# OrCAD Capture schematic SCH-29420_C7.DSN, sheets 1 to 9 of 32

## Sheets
1 P01_FRONT_PAGE: title: i.MX 8QM CPU CARD; rev: C7; company: NXP Semiconductors; note: SOURCE: SCH-29420, PDF: SPF-29420; note: 6501 William Cannon Drive West; note: Austin, TX 78735-8598
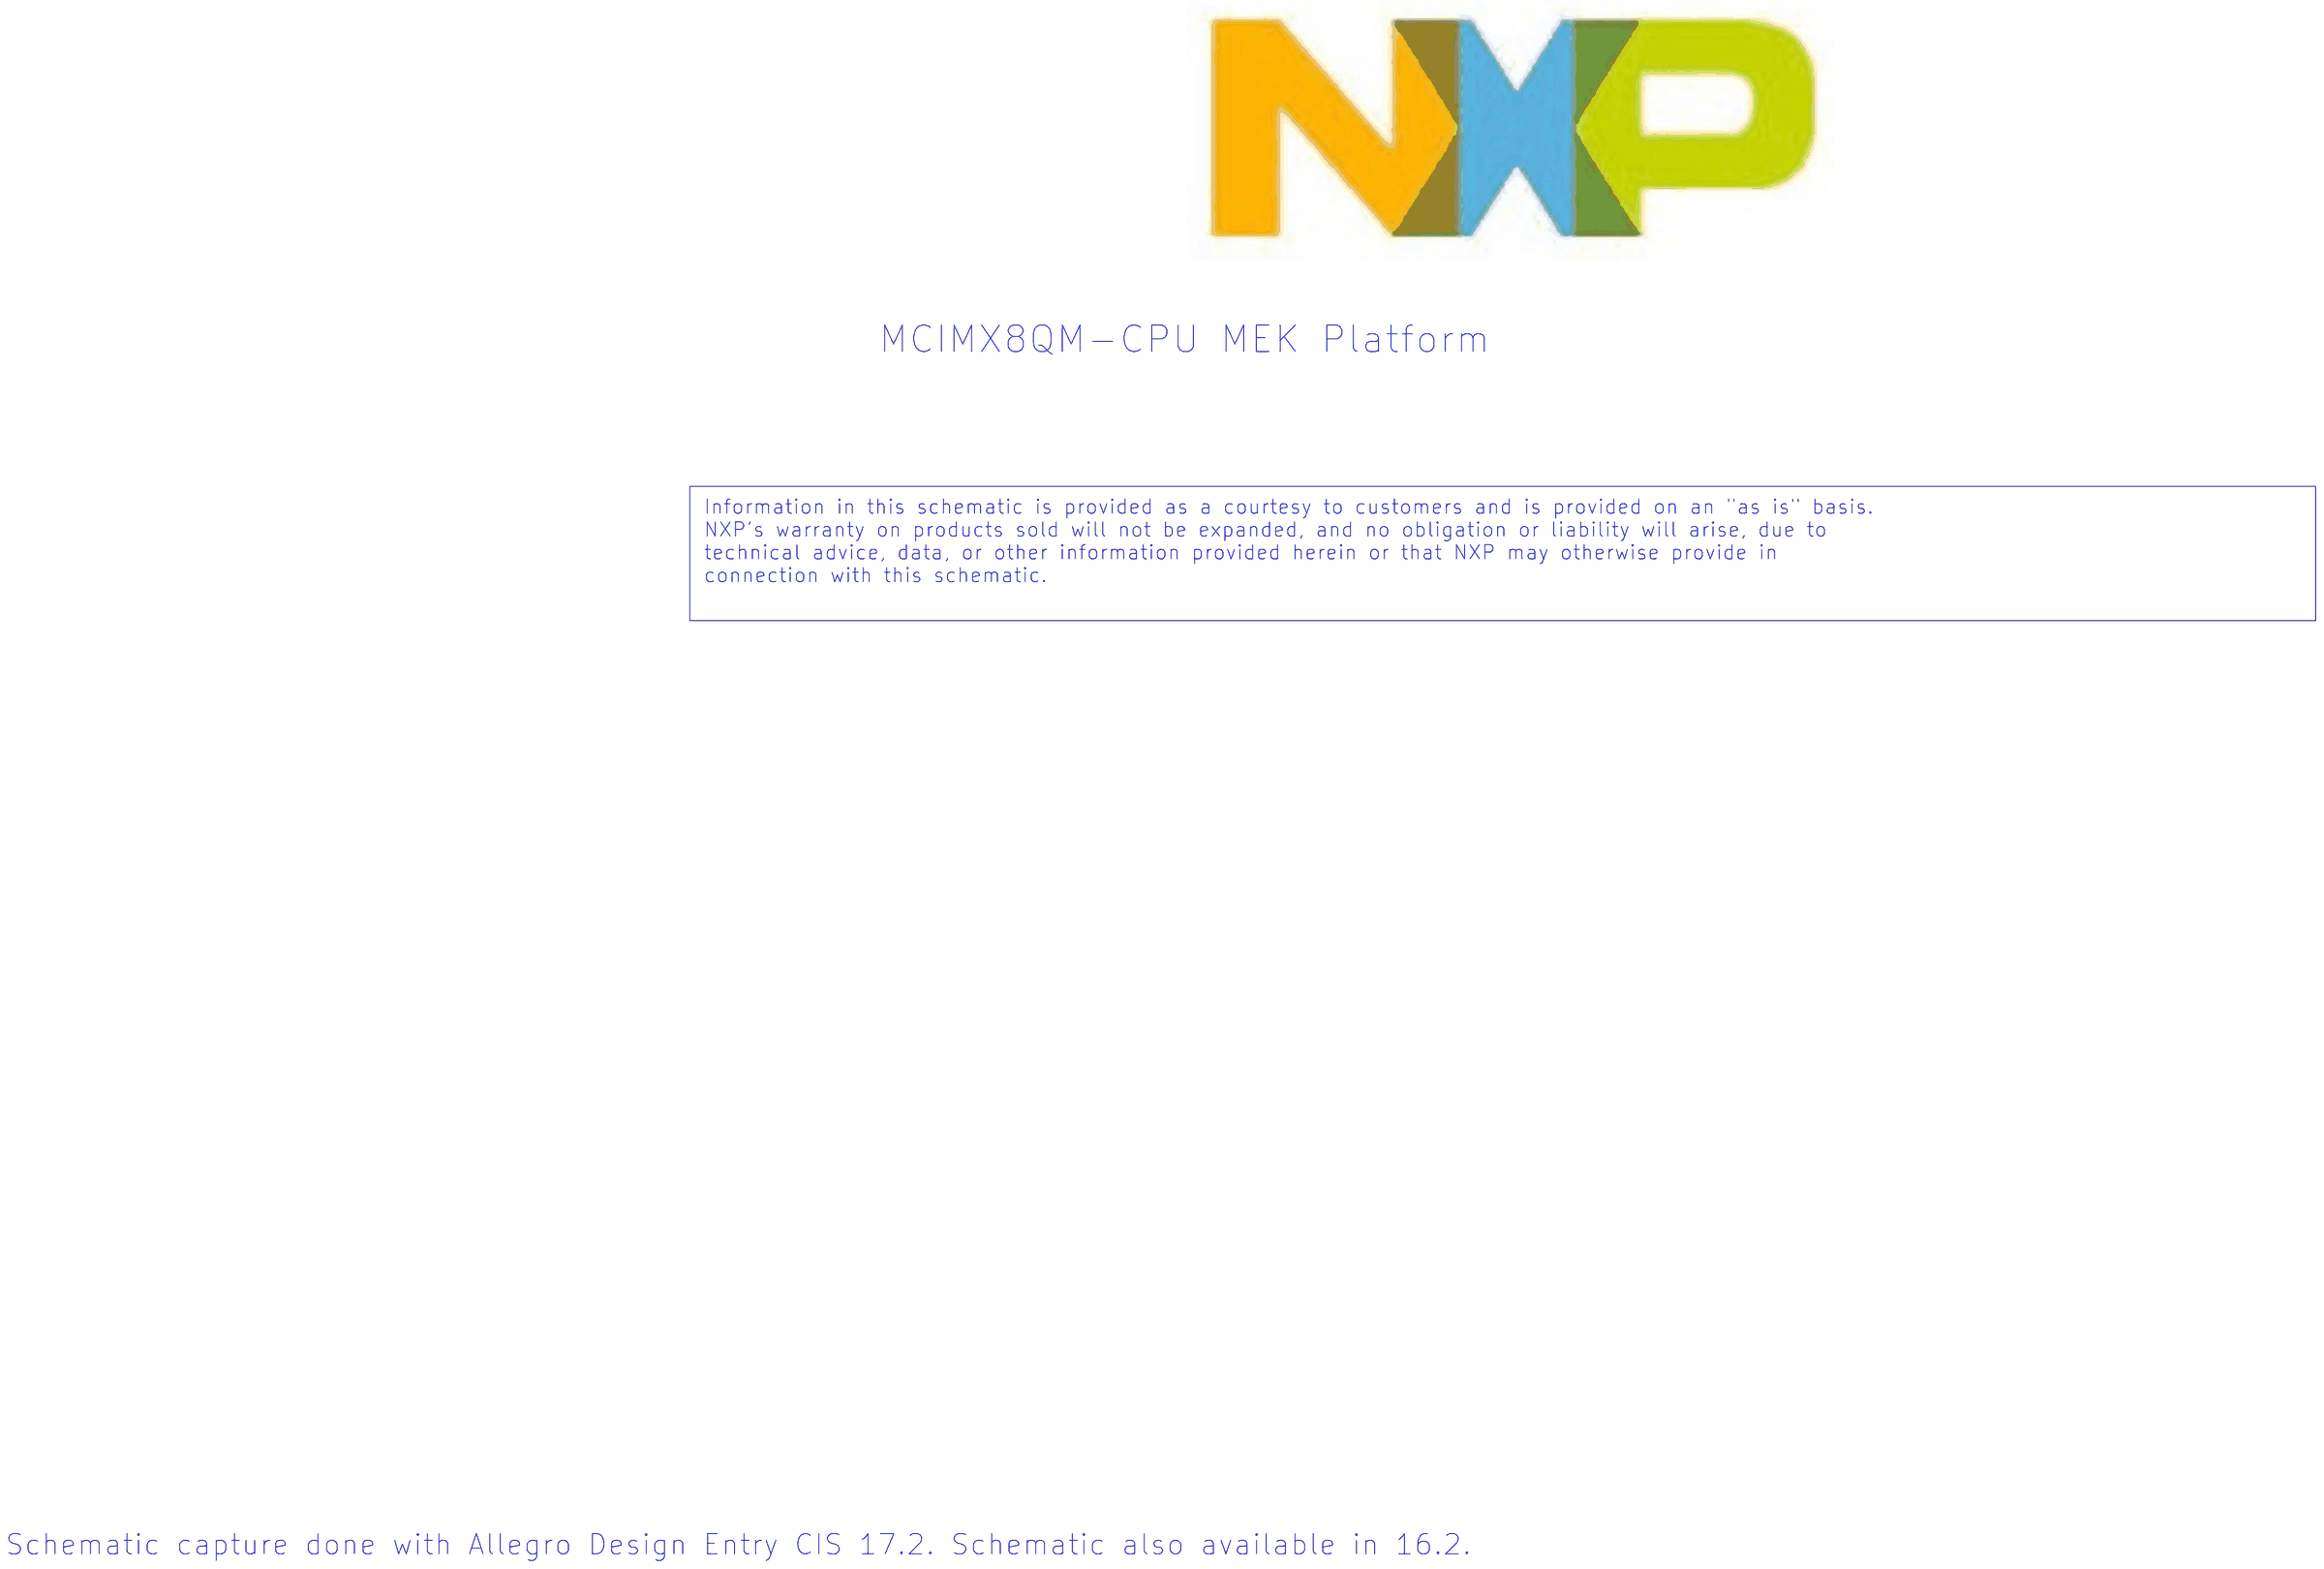
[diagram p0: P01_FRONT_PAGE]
2 P30_B2B_CONNETOR: size A2
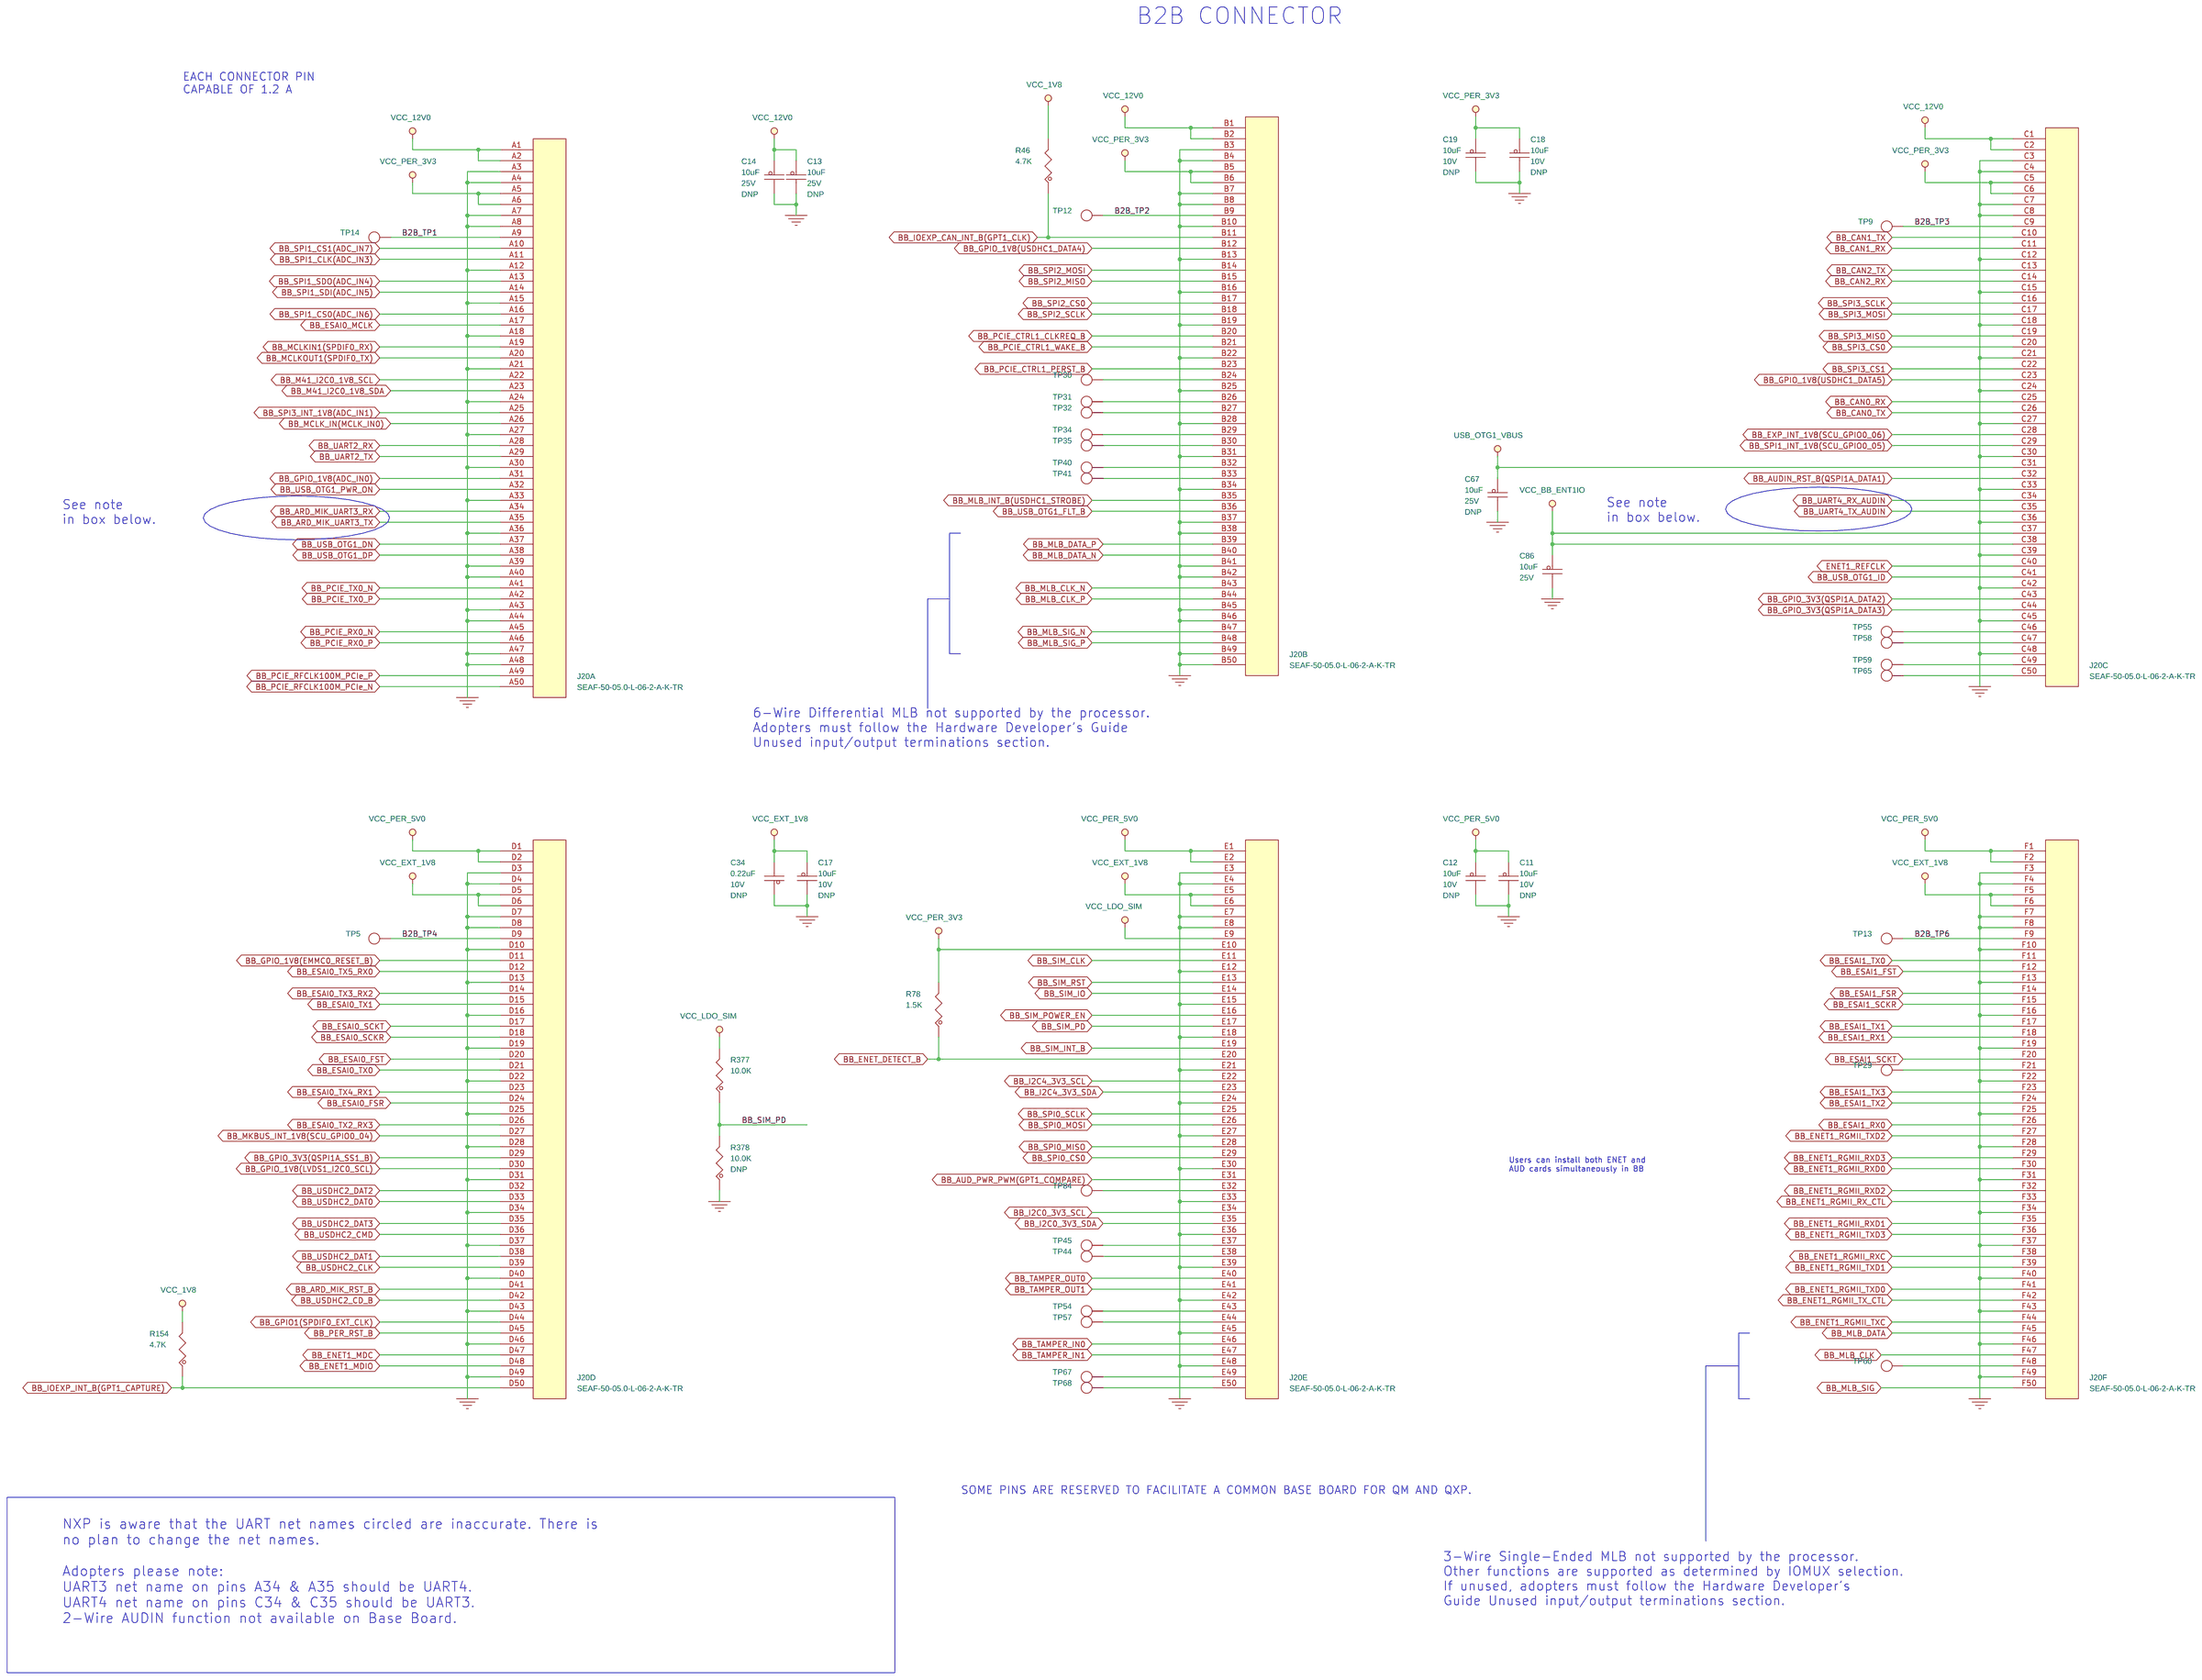
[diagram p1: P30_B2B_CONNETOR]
3 P06_I2C_TABLE
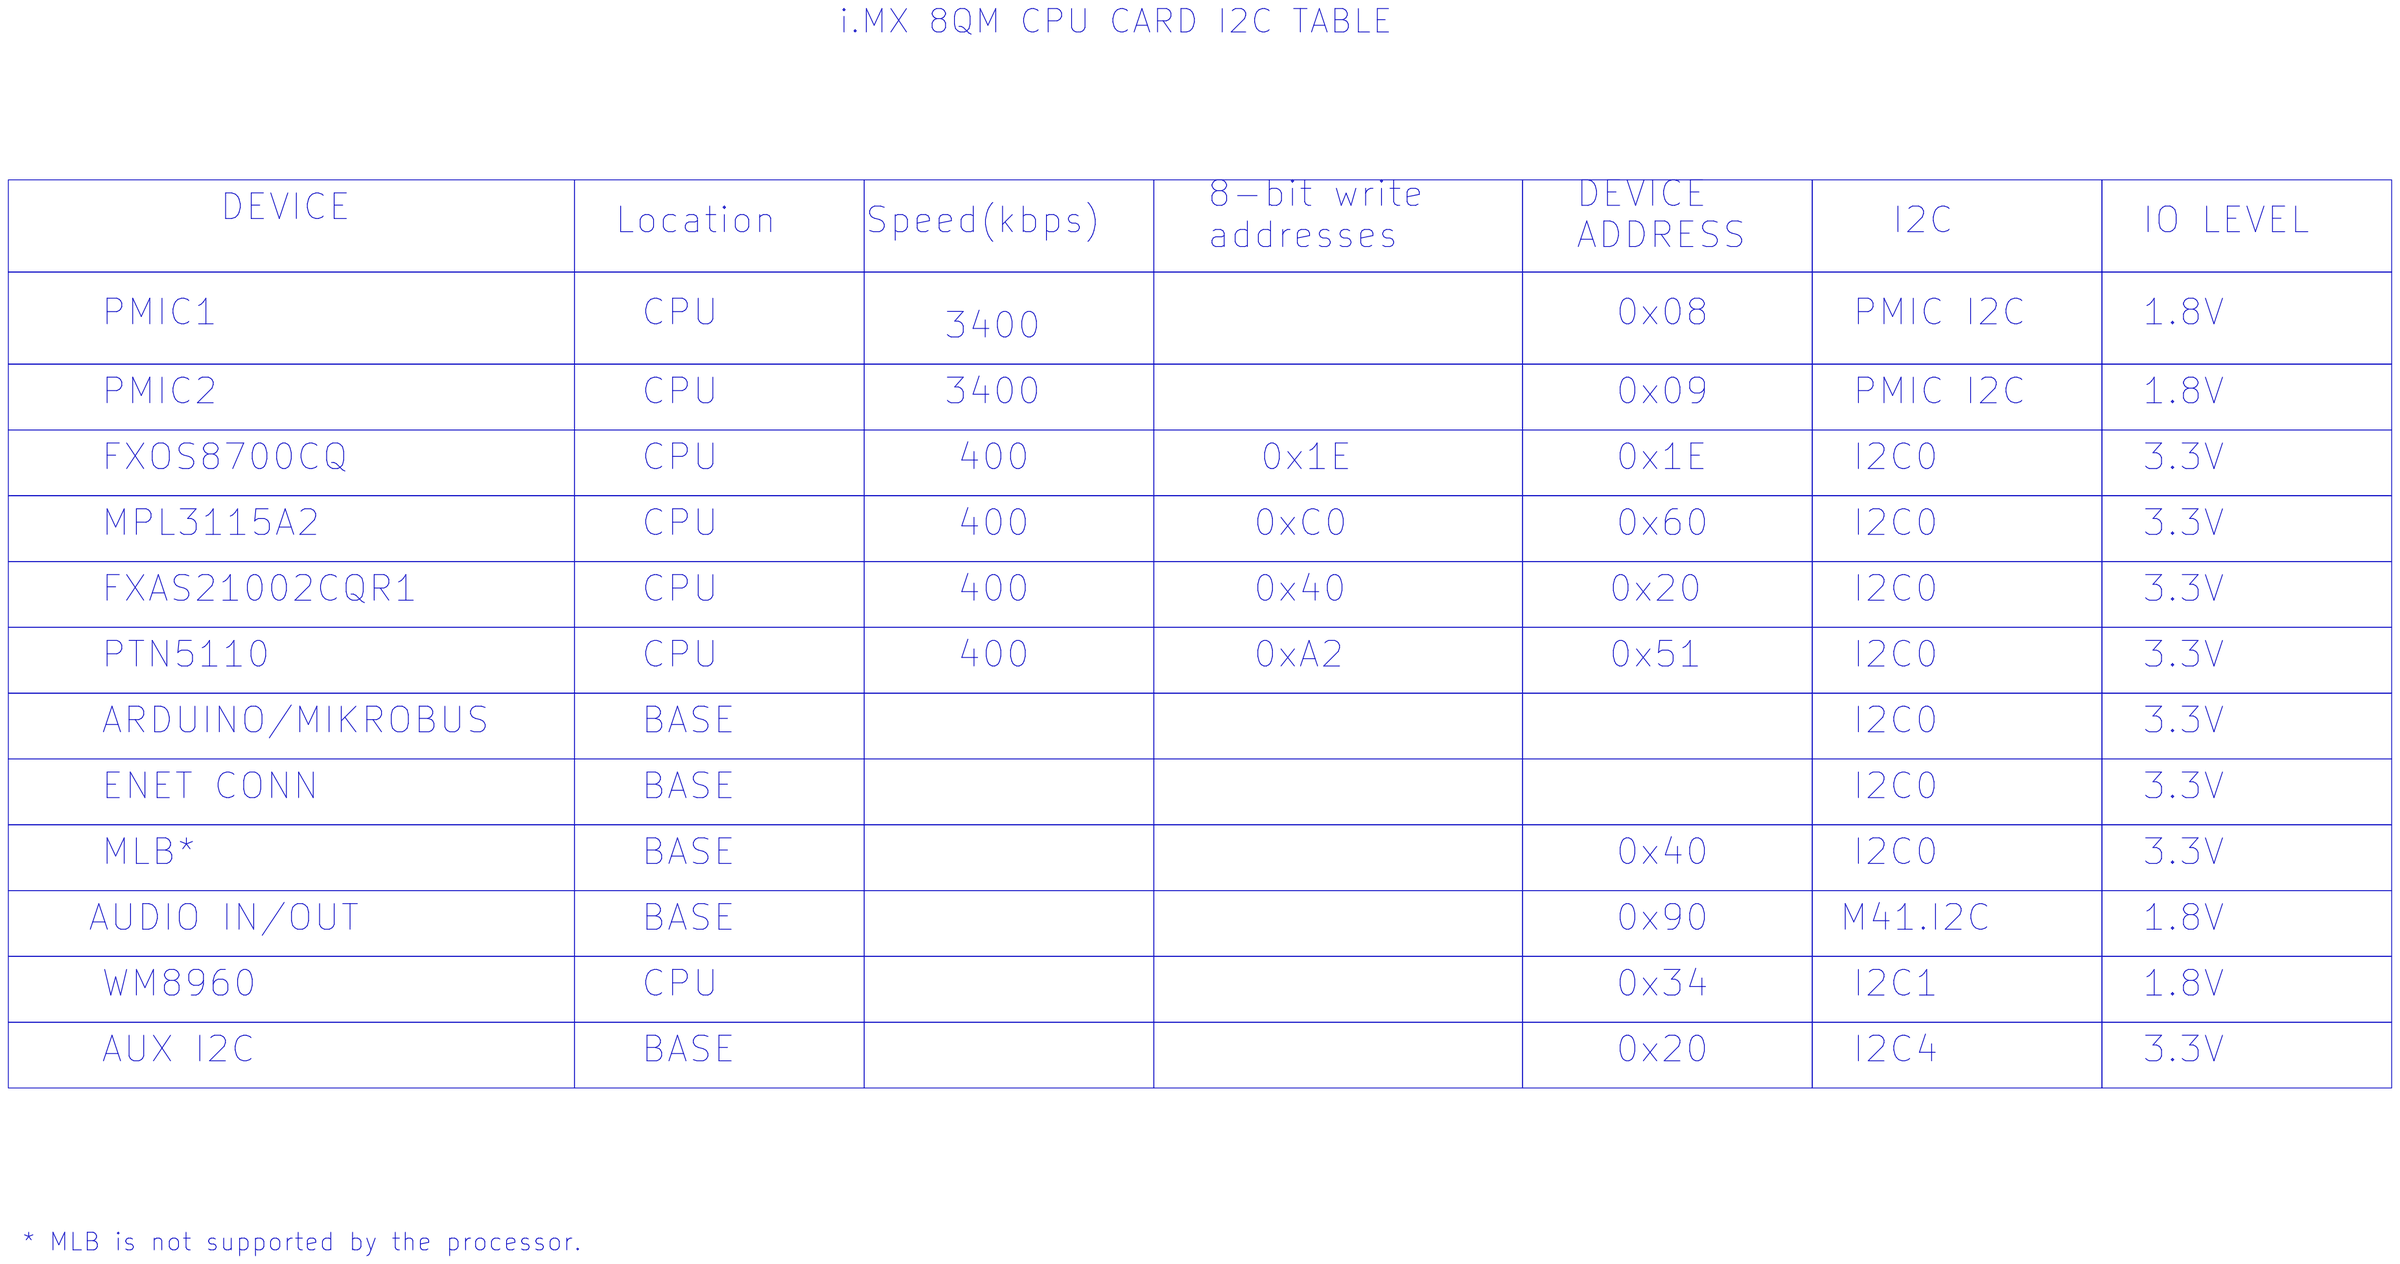
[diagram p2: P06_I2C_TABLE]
4 P05_BLOCK_DIAGRAM_RESET
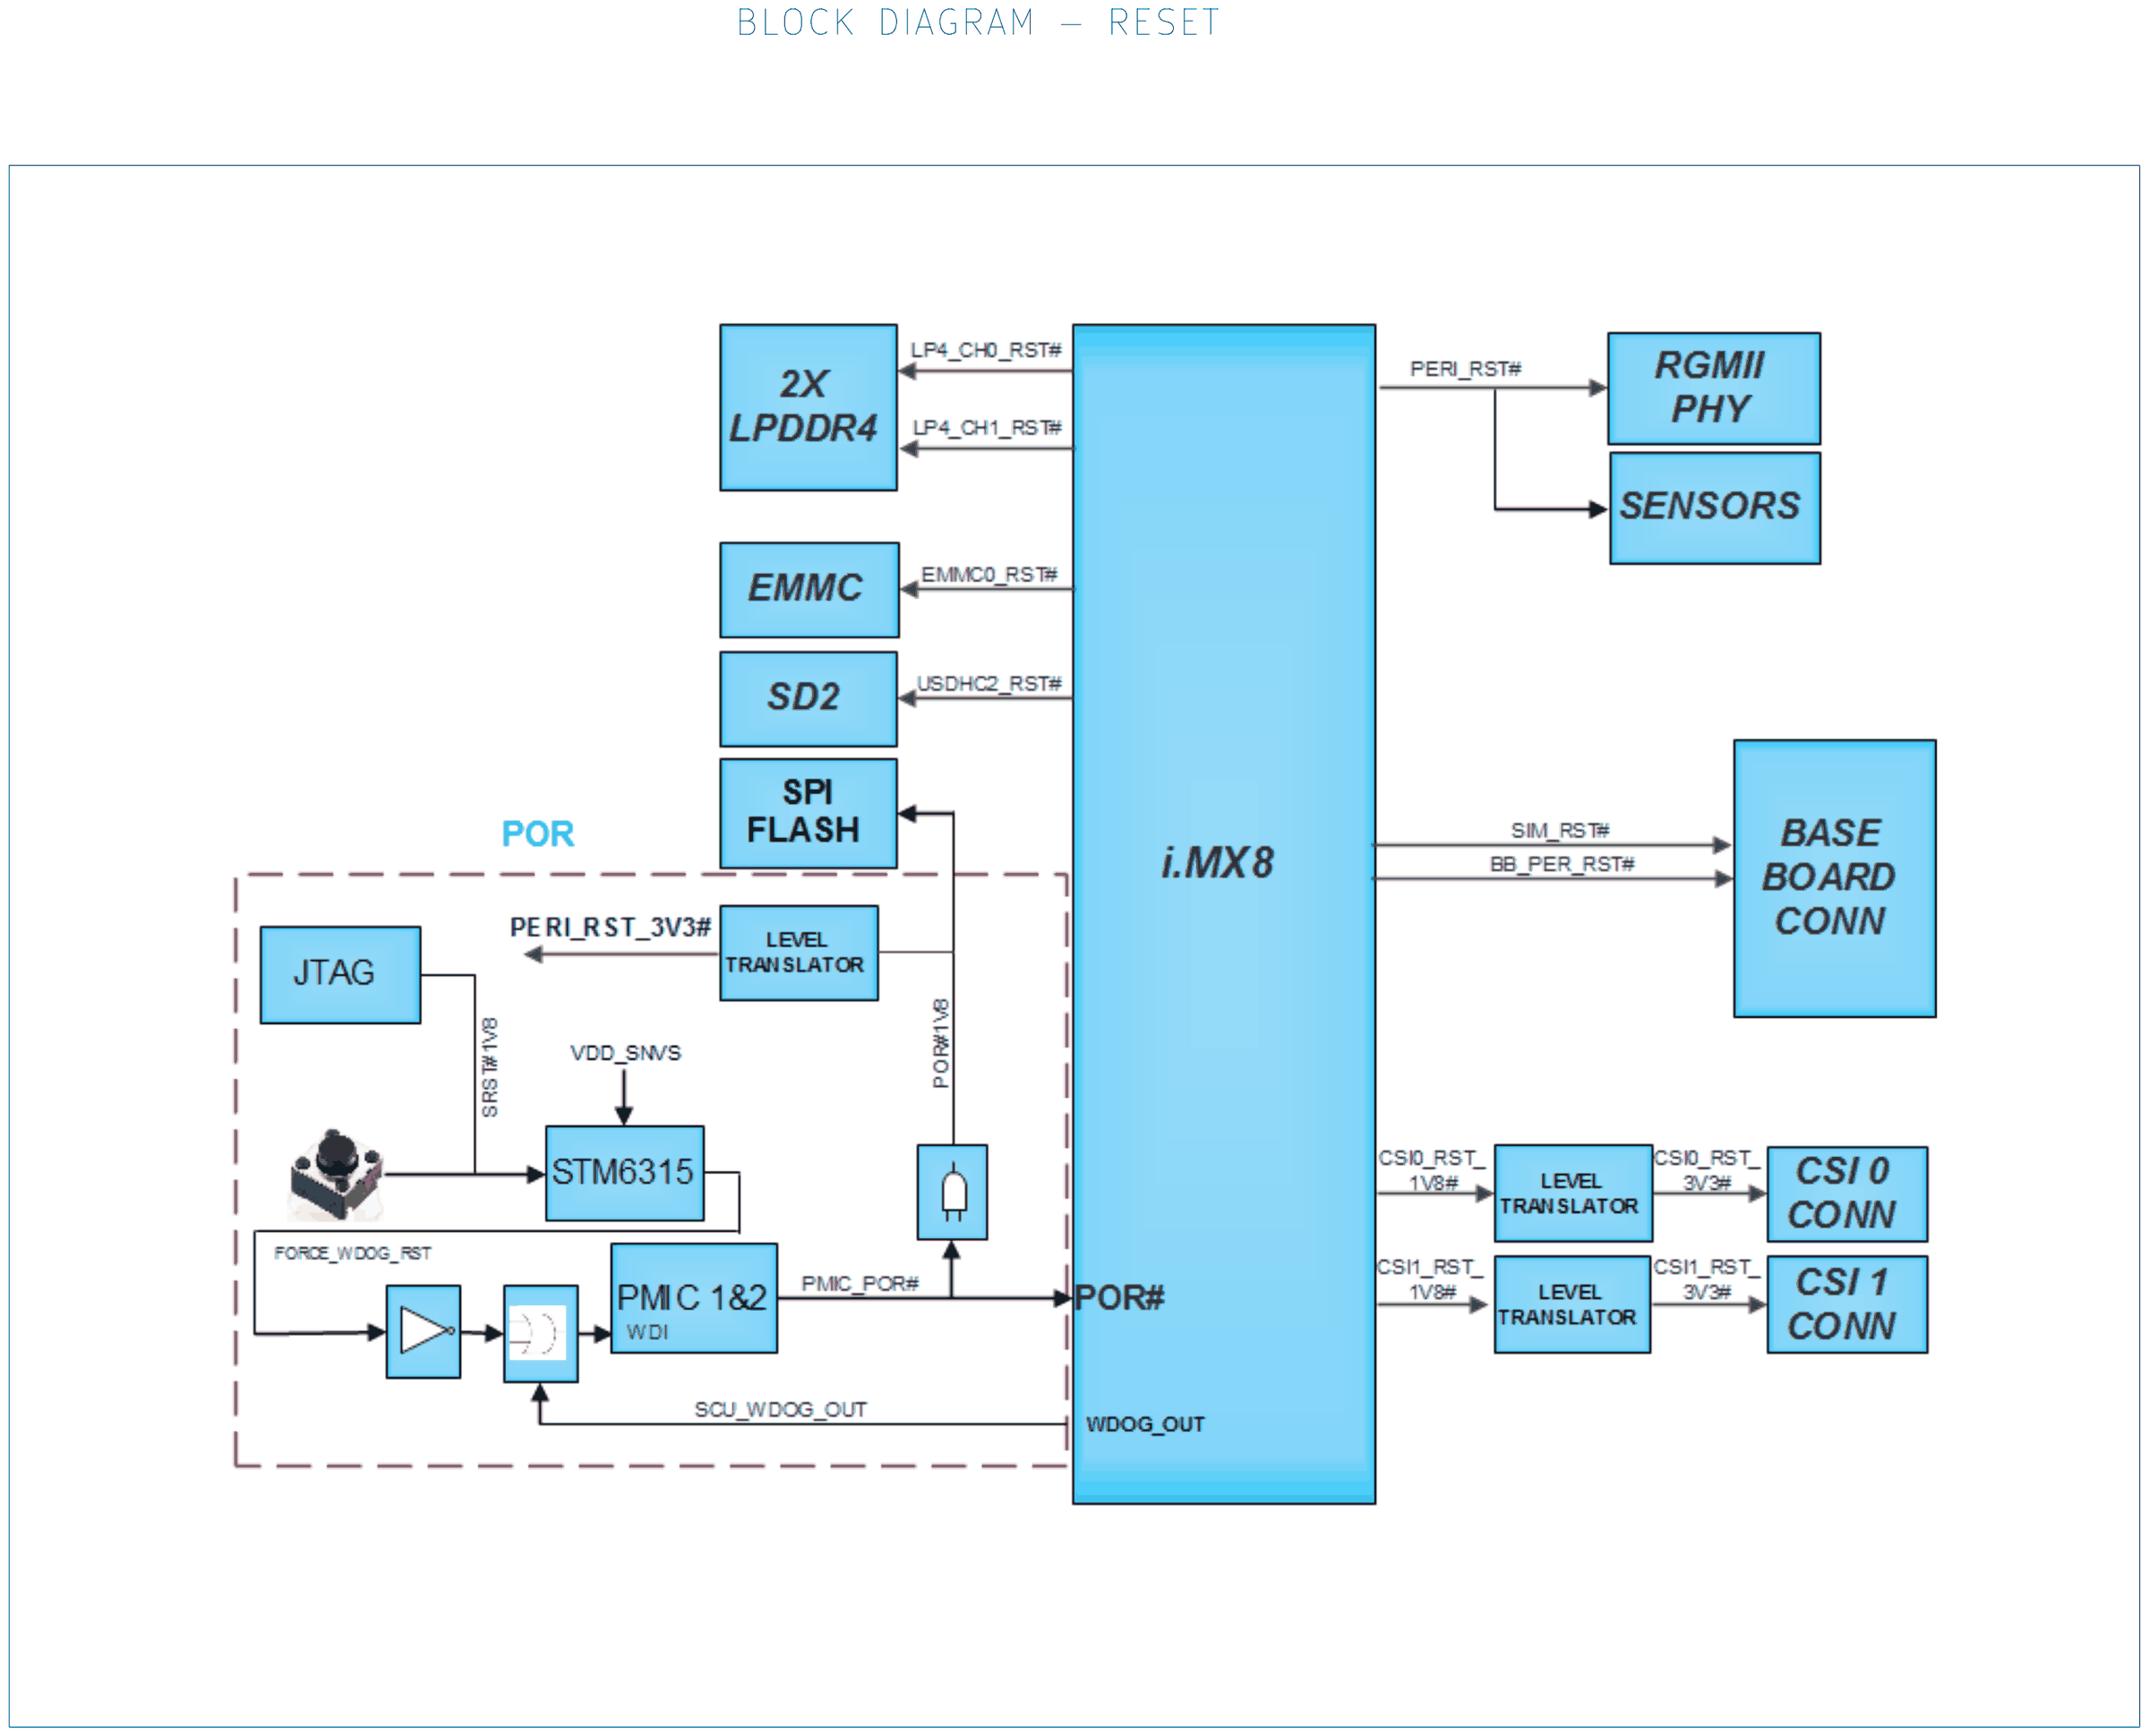
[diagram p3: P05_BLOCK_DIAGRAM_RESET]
5 P29_MIPI_DSI_CONNECTORS: size A2
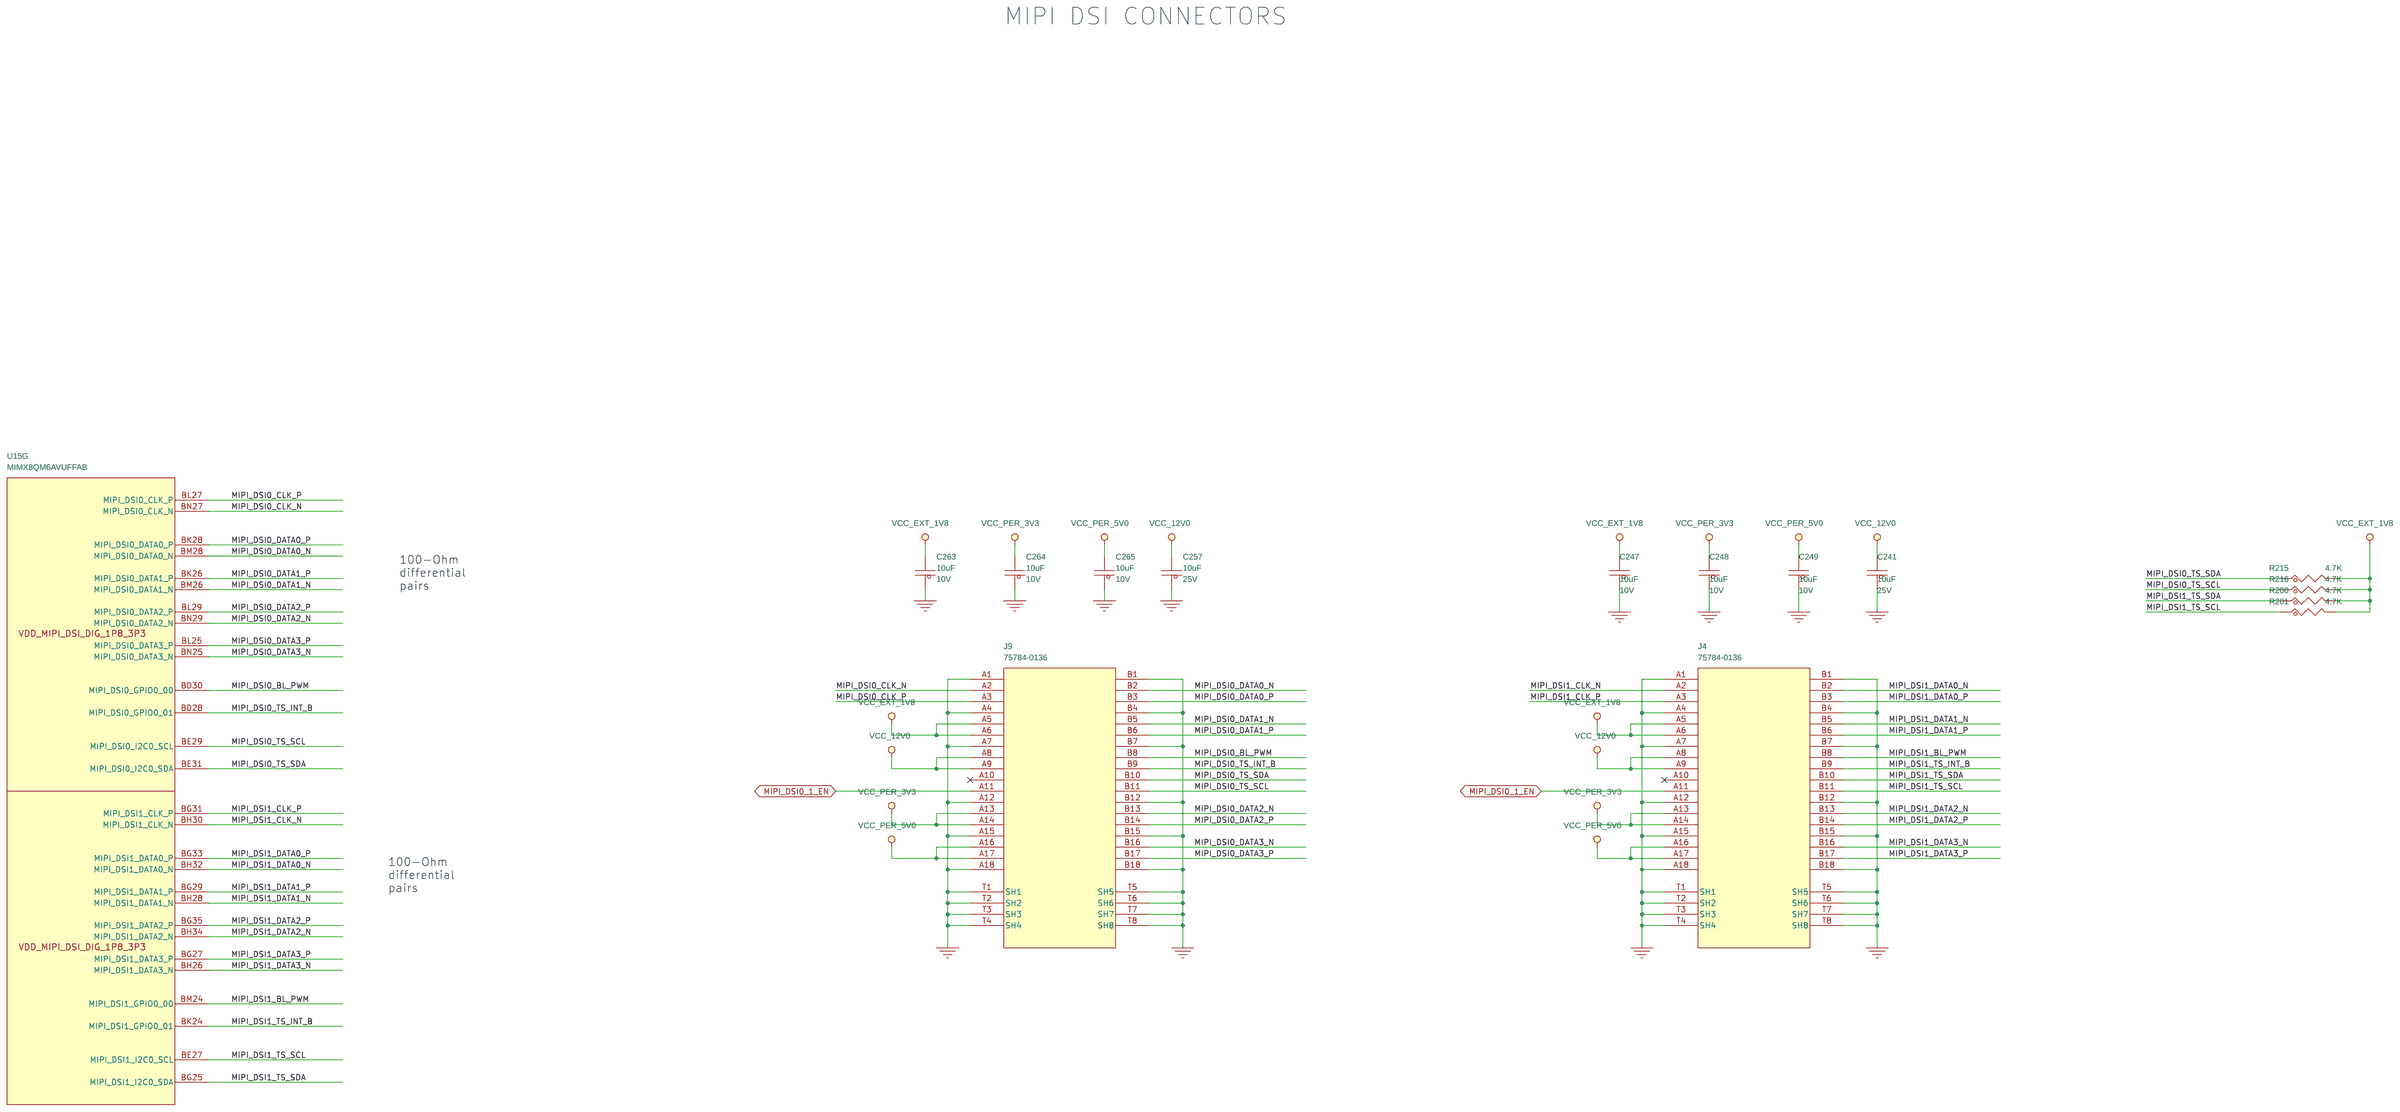
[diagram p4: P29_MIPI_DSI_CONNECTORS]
6 P09_PMIC_2: size A2
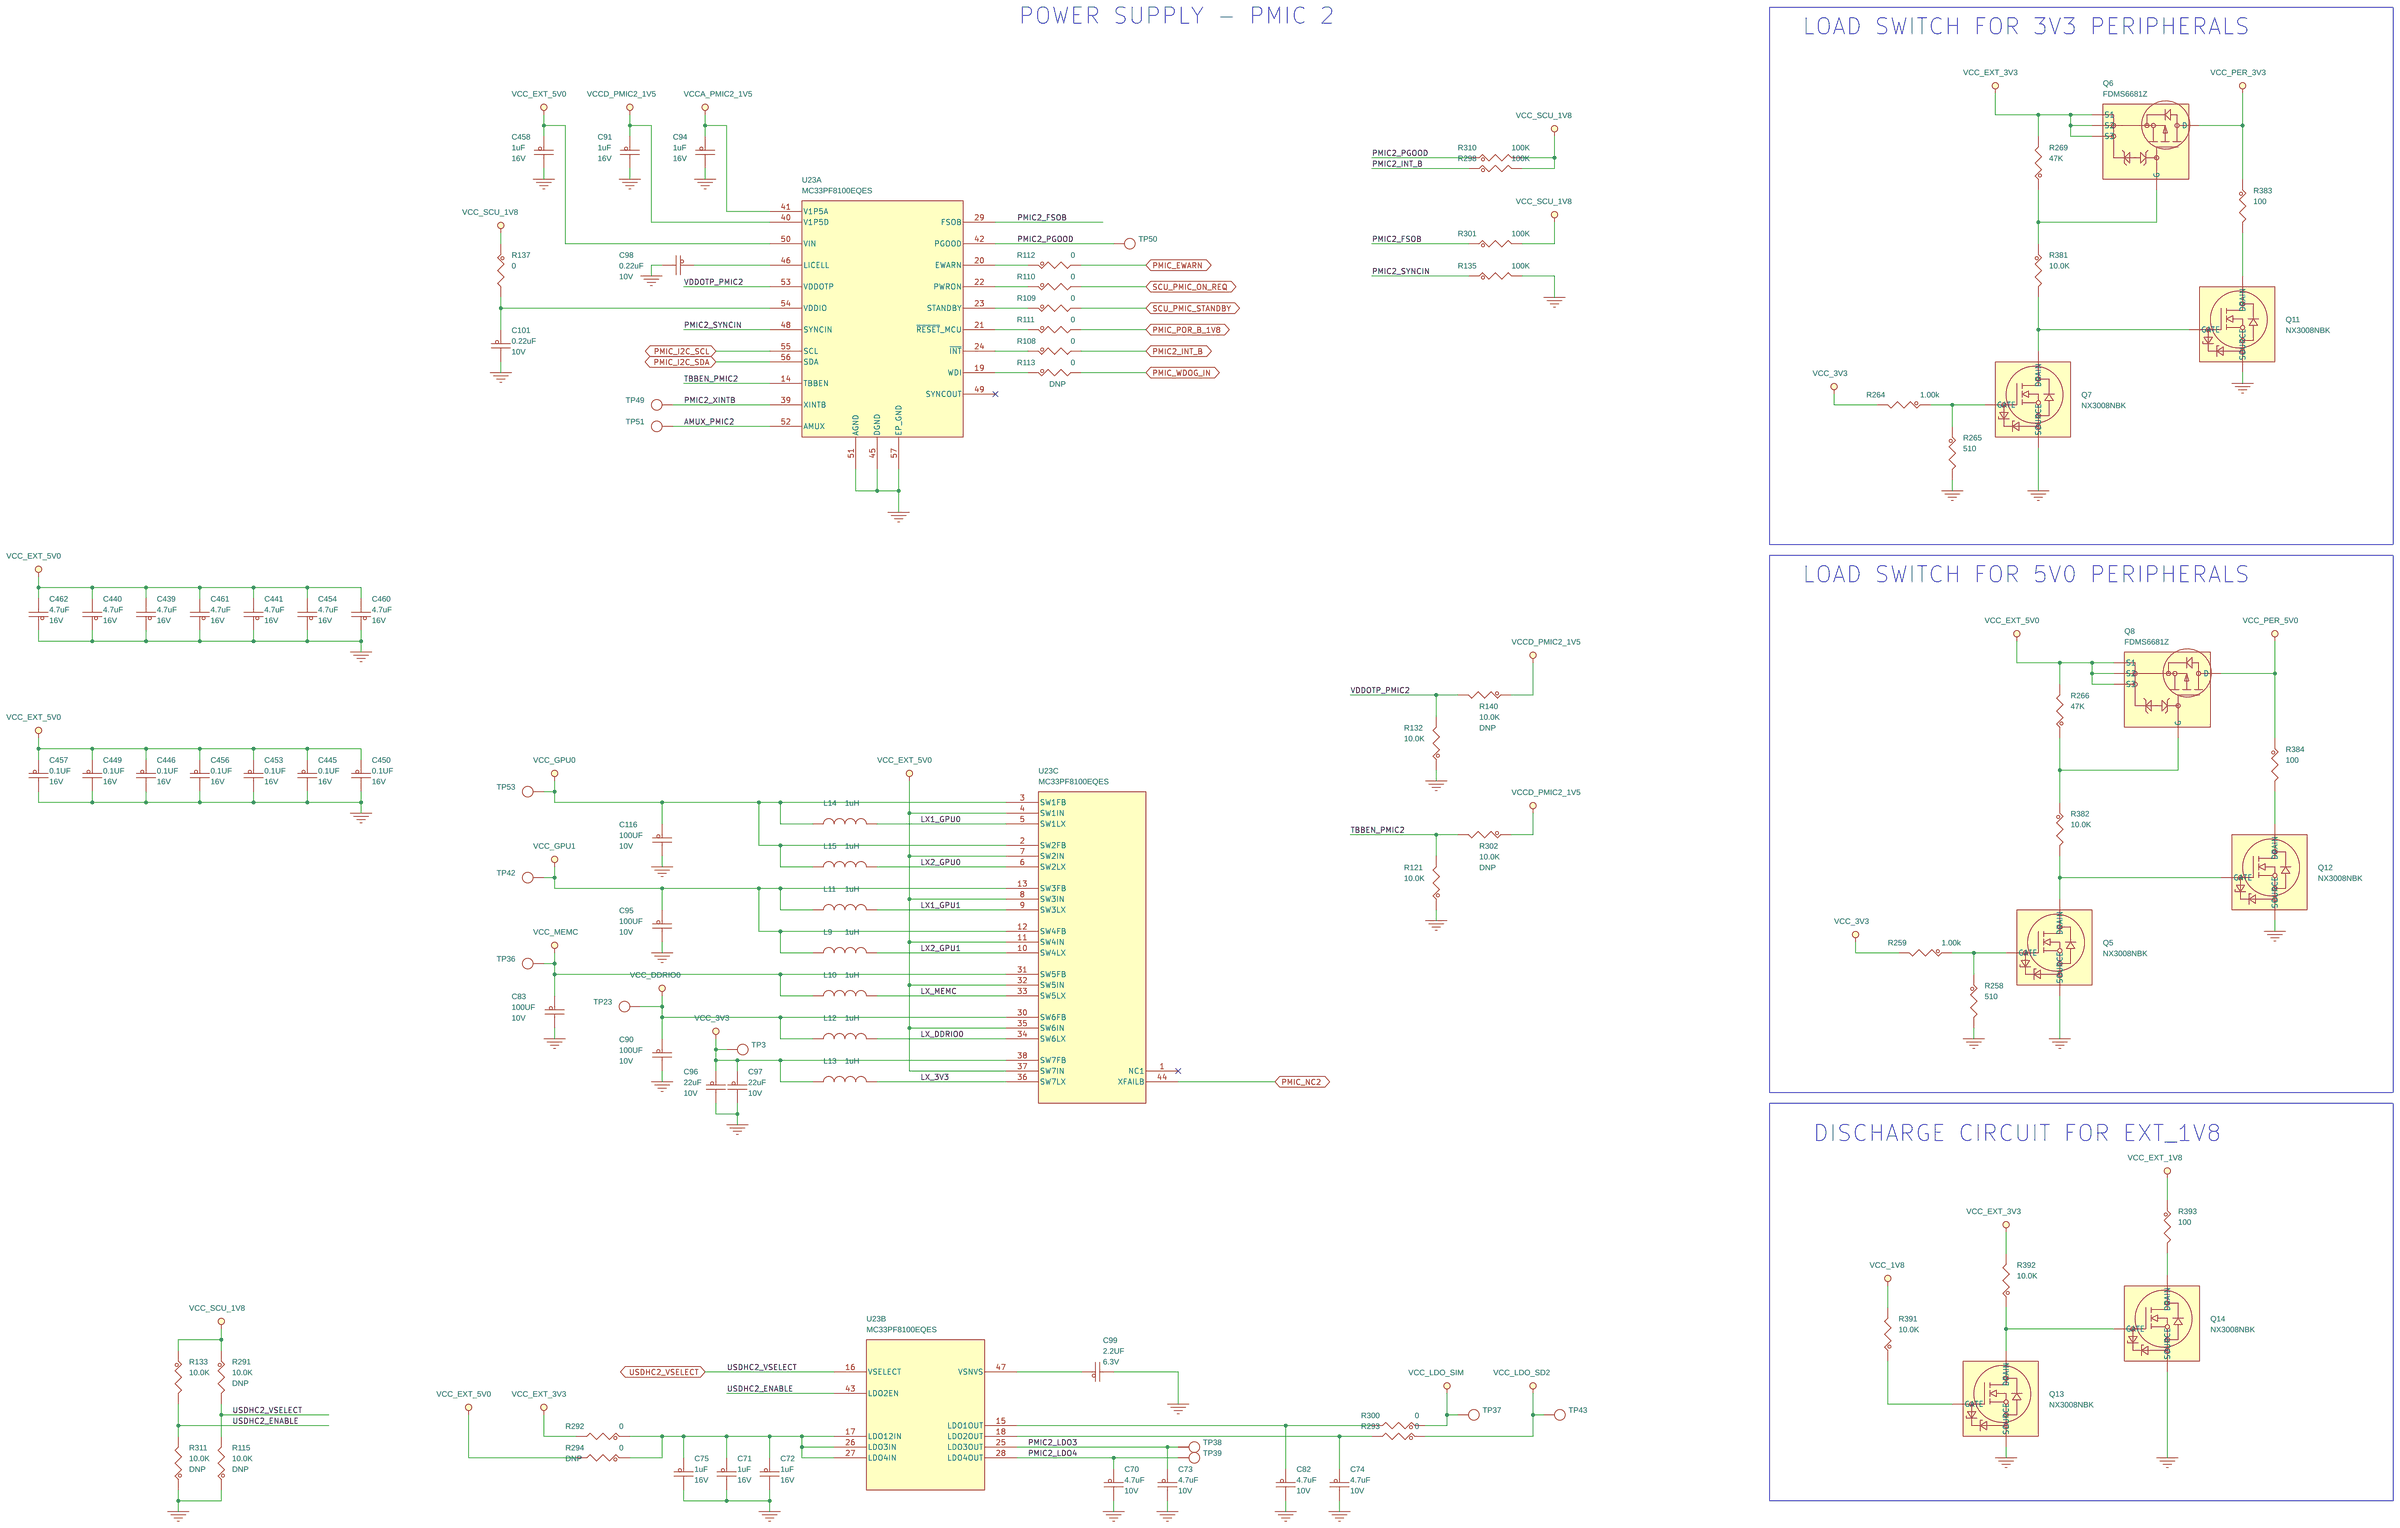
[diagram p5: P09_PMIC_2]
7 P04_BLOCK_DIAGRAM_POWER
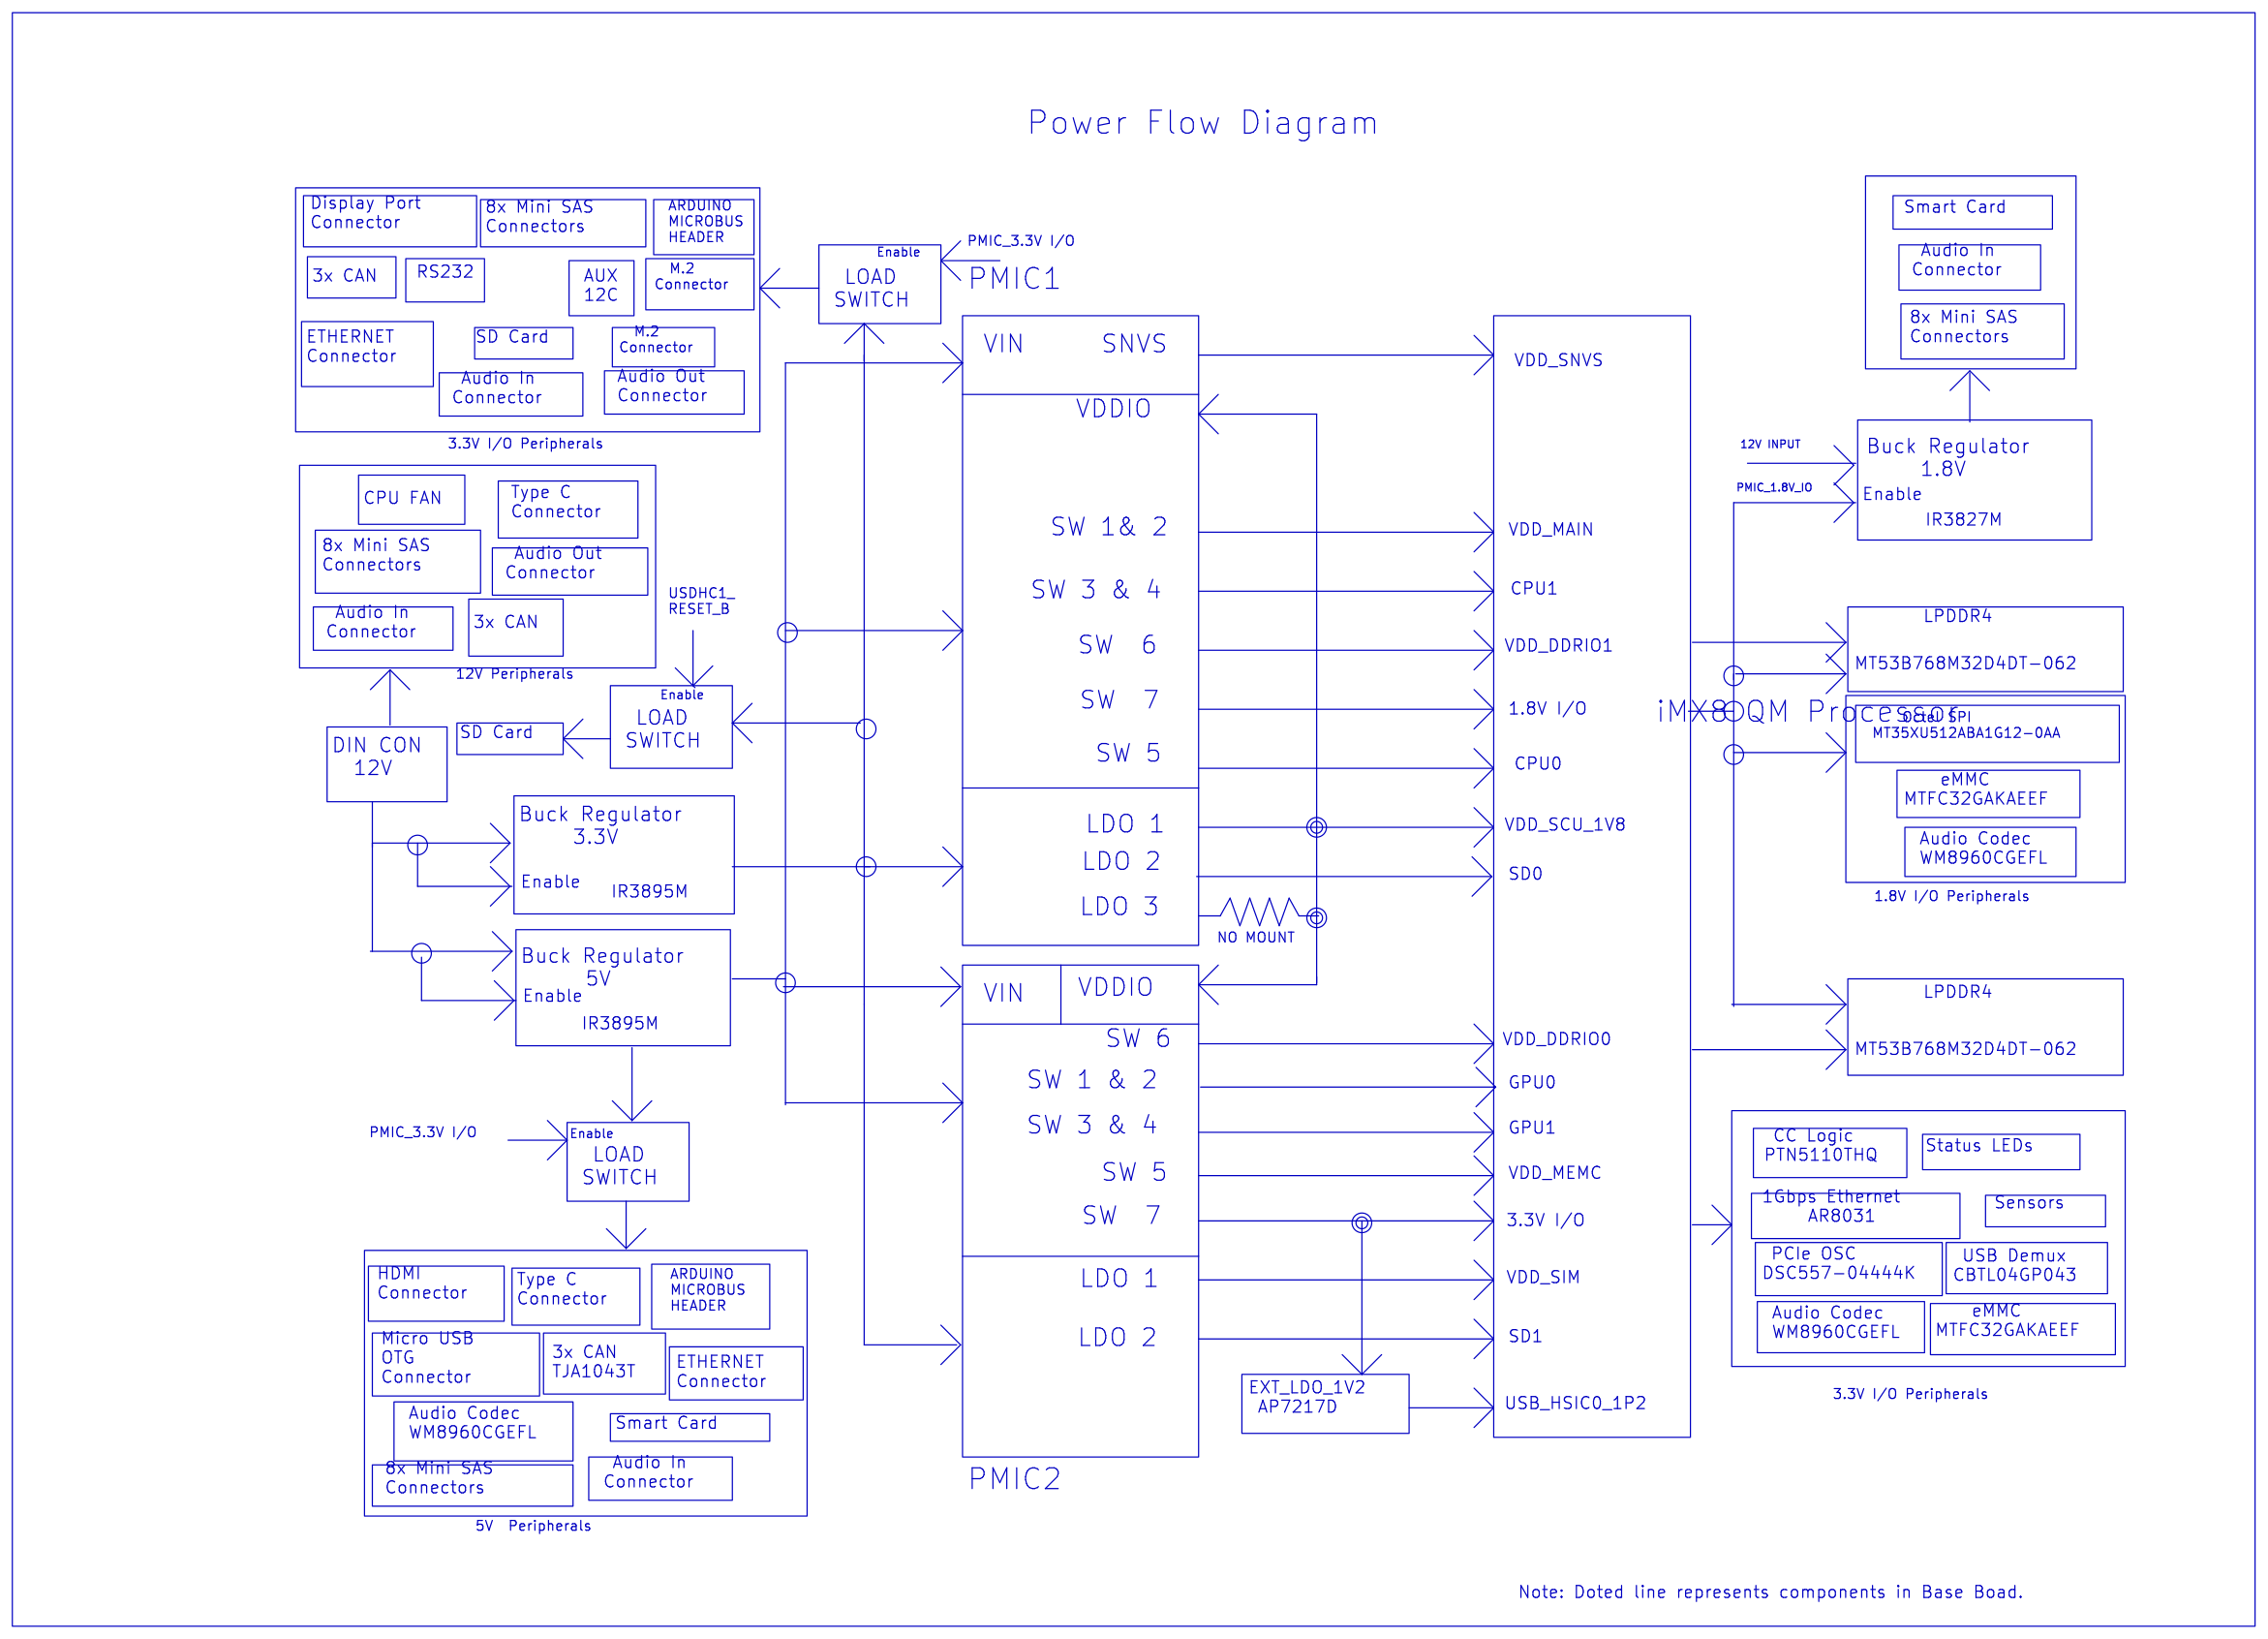
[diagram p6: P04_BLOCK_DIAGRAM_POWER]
8 P02_TITLE_PAGE
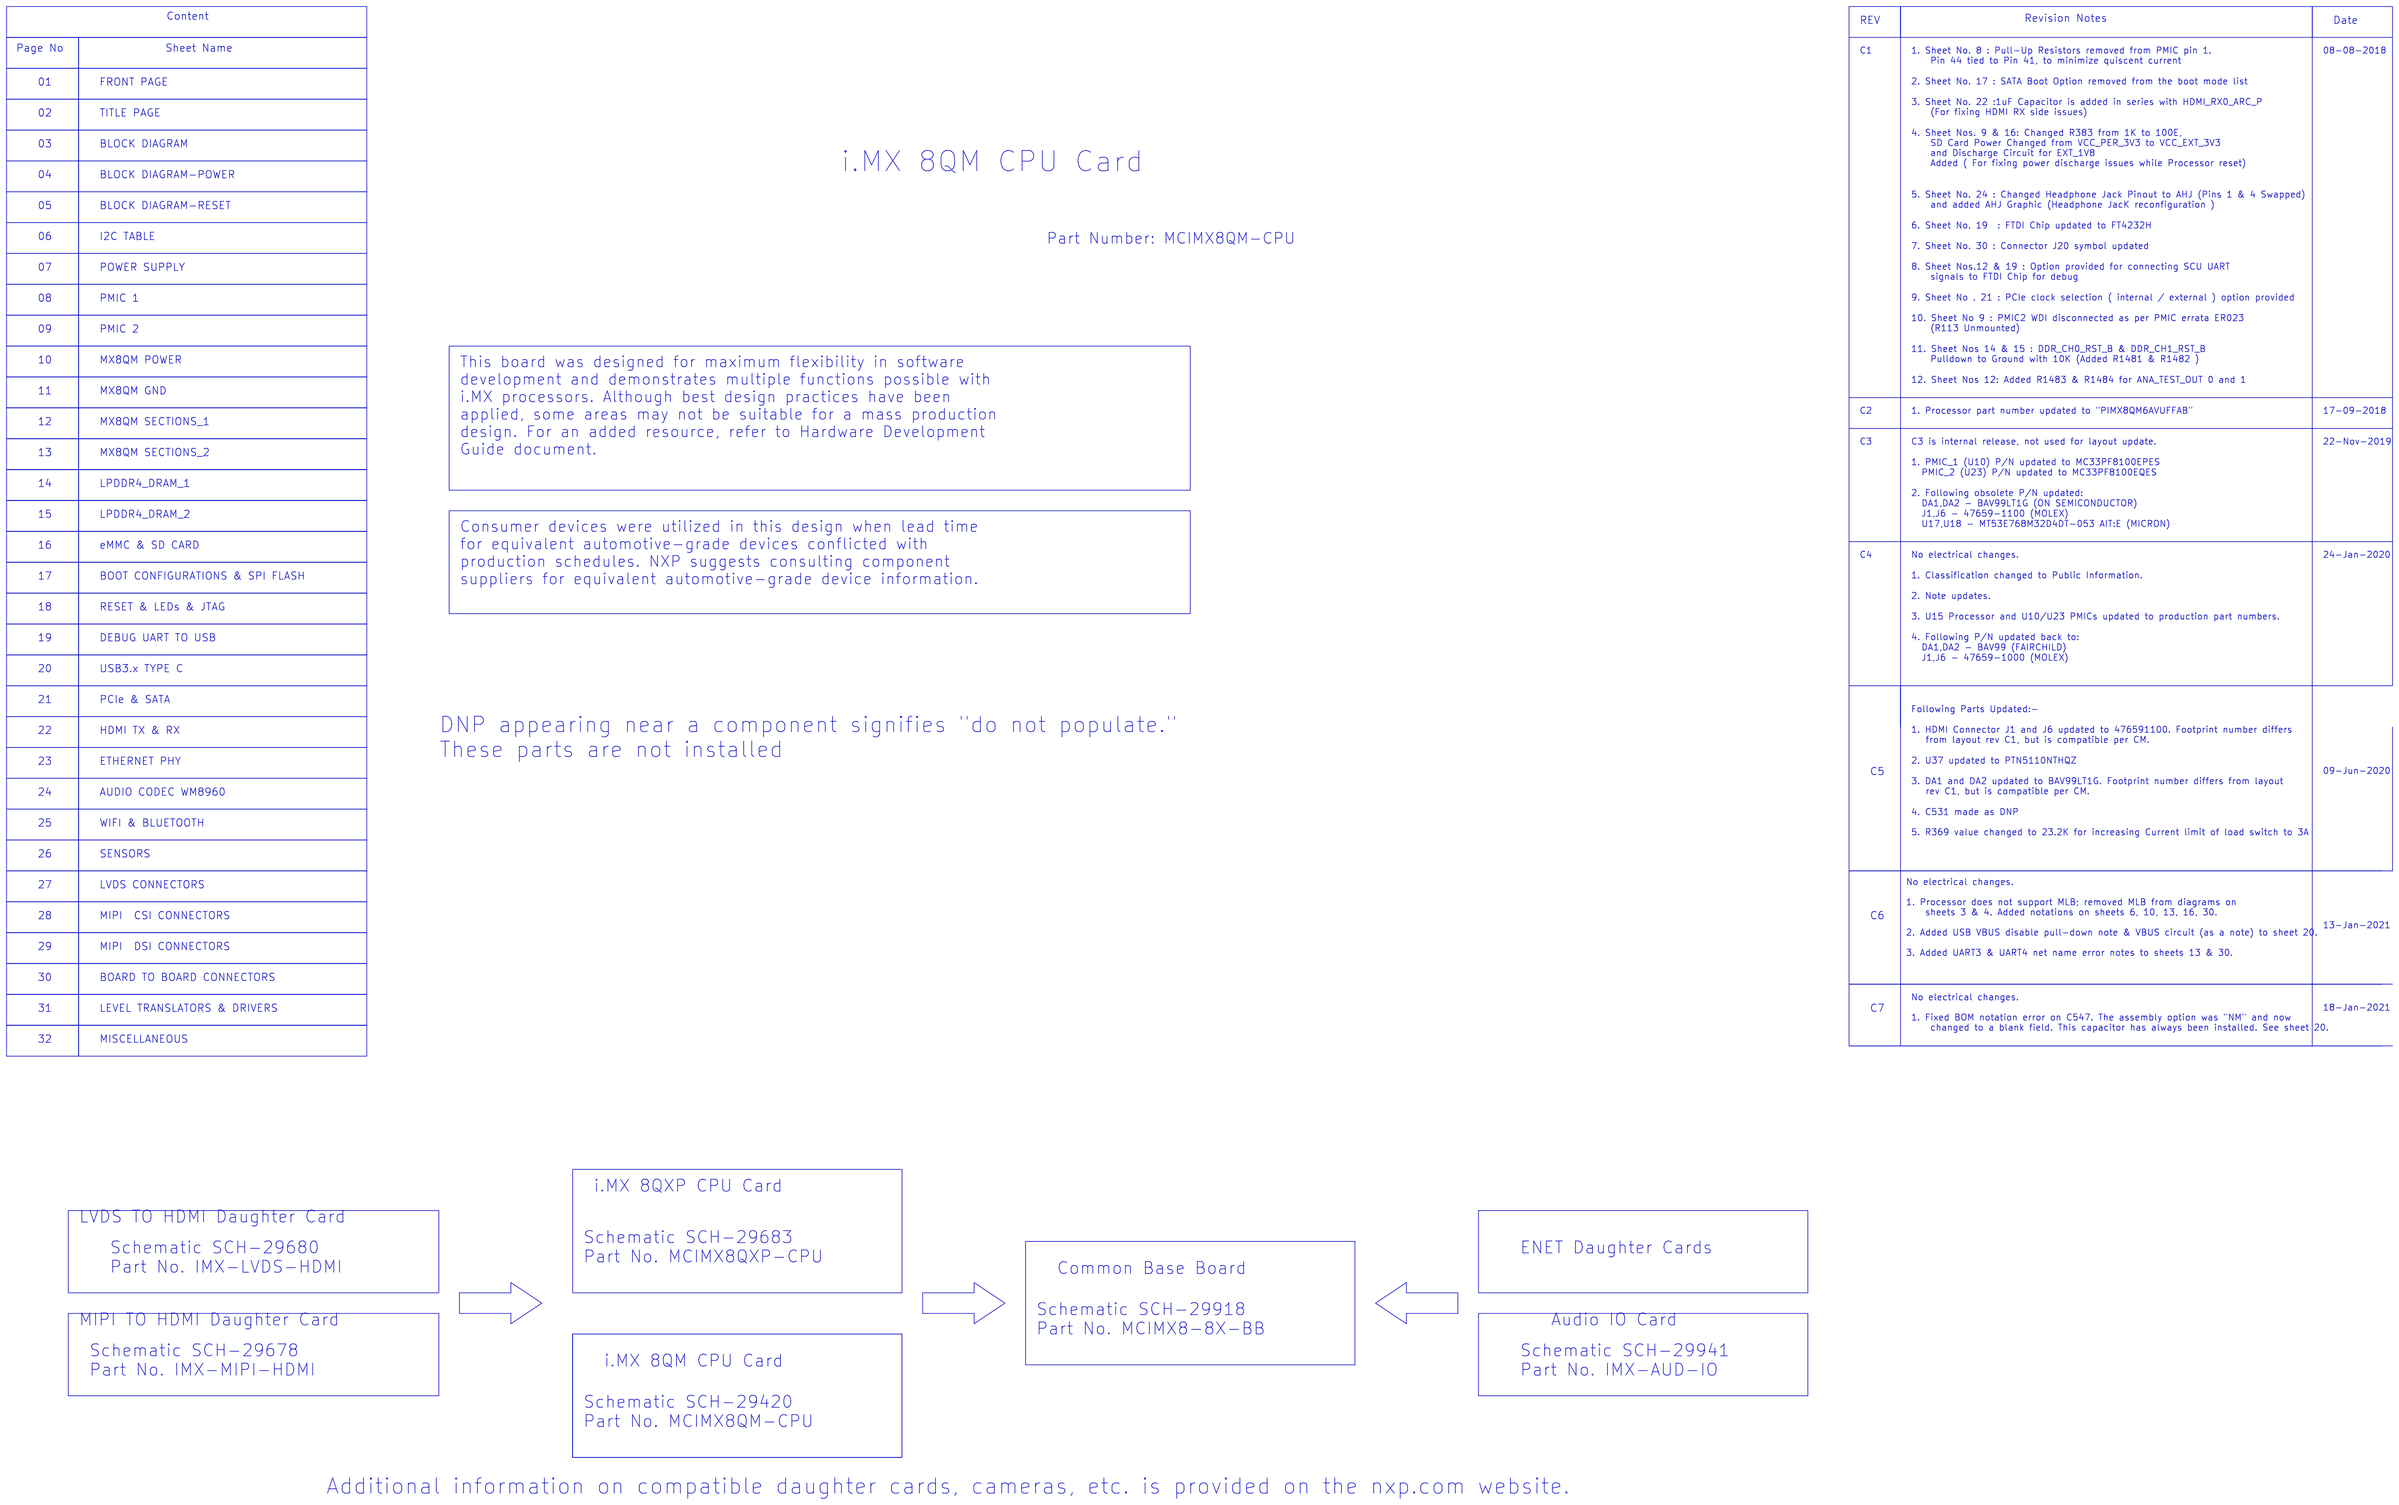
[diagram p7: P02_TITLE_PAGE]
9 P03_BLOCK_DIAGRAM
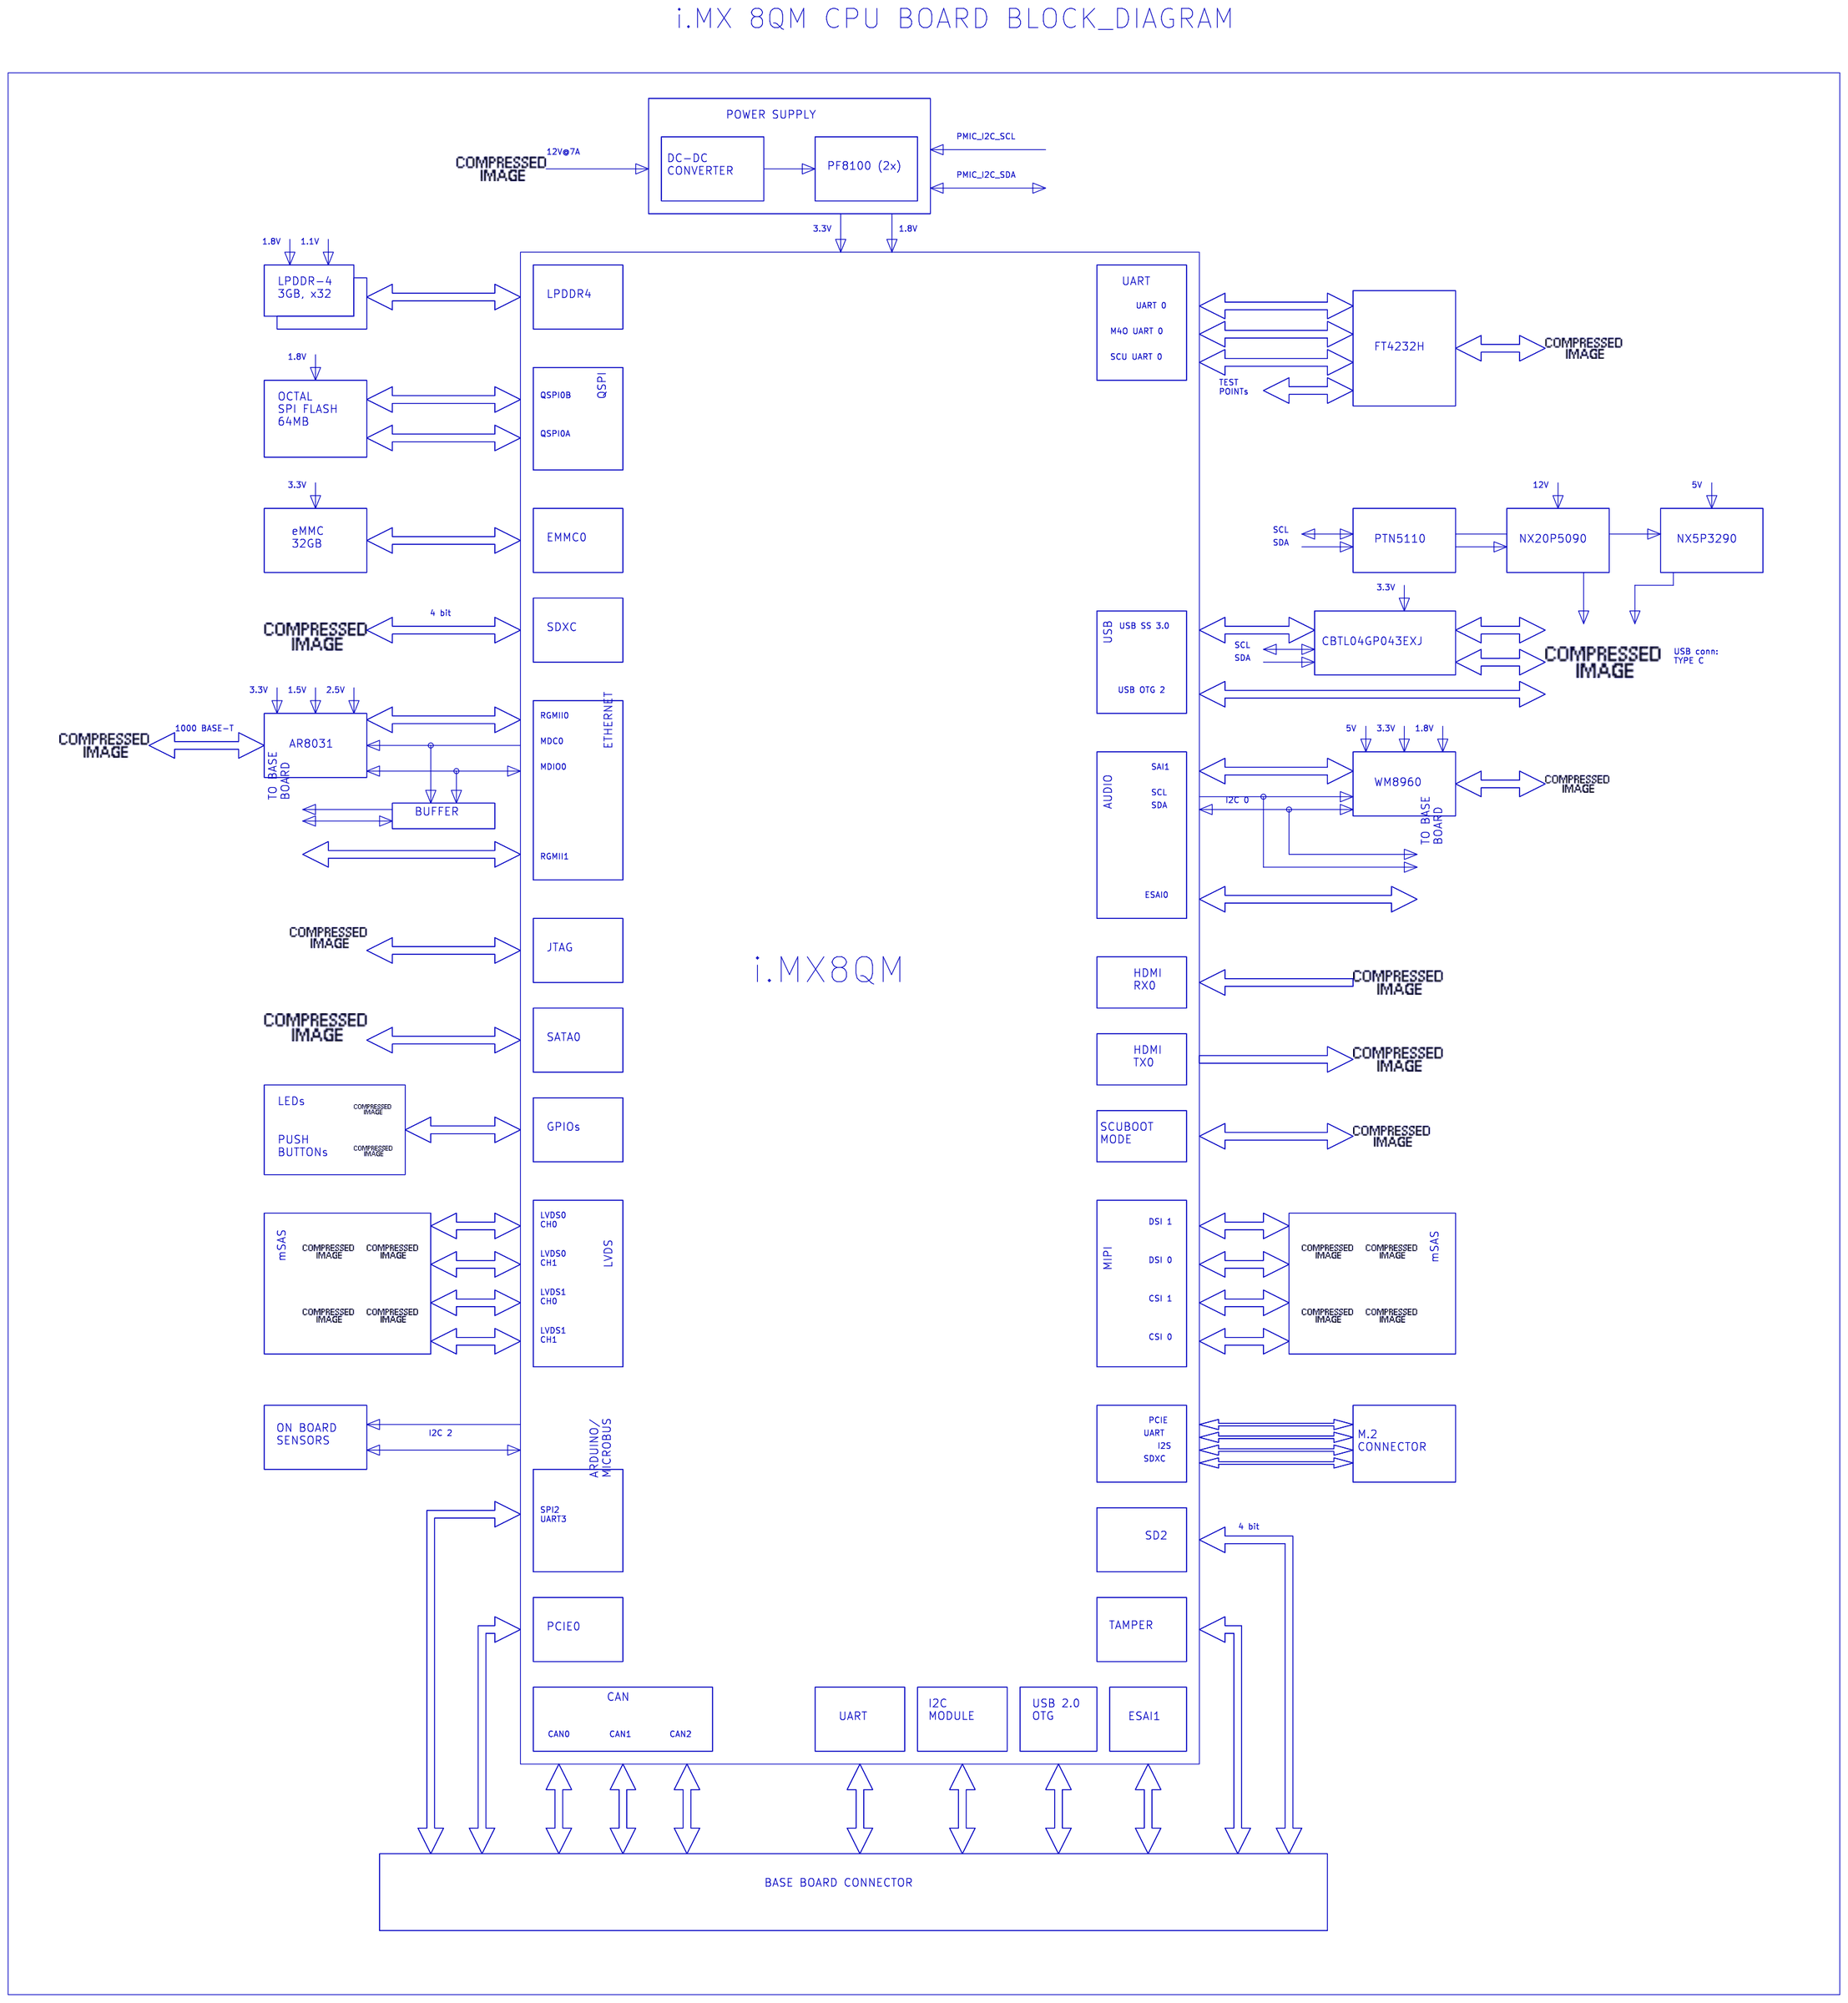
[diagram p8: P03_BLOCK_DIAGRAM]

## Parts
sheet P09_PMIC_2
C70  4.7uF  [CC0402_25]
C71  1uF  [CC0402_25]
C72  1uF  [CC0402_25]
C73  4.7uF  [CC0402_25]
C74  4.7uF  [CC0402_25]
C75  1uF  [CC0402_25]
C82  4.7uF  [CC0402_25]
C83  100UF  [CC1210]
C90  100UF  [CC1210]
C91  1uF  [CC0402_25]
C94  1uF  [CC0402_25]
C95  100UF  [CC1210]
C96  22uF  [CC0603_OV]
C97  22uF  [CC0603_OV]
C98  0.22uF  [CC0402_25]
C99  2.2UF  [CC0402_25]
C101  0.22uF  [CC0402_25]
C116  100UF  [CC1210]
C439  4.7uF  [CC0603_OV]
C440  4.7uF  [CC0603_OV]
C441  4.7uF  [CC0603_OV]
C445  0.1UF  [CC0402_25]
C446  0.1UF  [CC0402_25]
C449  0.1UF  [CC0402_25]
C450  0.1UF  [CC0402_25]
C453  0.1UF  [CC0402_25]
C454  4.7uF  [CC0603_OV]
C456  0.1UF  [CC0402_25]
C457  0.1UF  [CC0402_25]
C458  1uF  [CC0402_25]
C460  4.7uF  [CC0603_OV]
C461  4.7uF  [CC0603_OV]
C462  4.7uF  [CC0603_OV]
L9  1uH  [ind2520]
L10  1uH  [ind2520]
L11  1uH  [ind2520]
L12  1uH  [ind2520]
L13  1uH  [ind2520]
L14  1uH  [ind2520]
L15  1uH  [ind2520]
Q5  NX3008NBK  [SOT23_A]
Q6  FDMS6681Z  [so8_pak]
Q7  NX3008NBK  [SOT23_A]
Q8  FDMS6681Z  [so8_pak]
Q11  NX3008NBK  [SOT23_A]
Q12  NX3008NBK  [SOT23_A]
Q13  NX3008NBK  [SOT23_A]
Q14  NX3008NBK  [SOT23_A]
R108  0  [RC0402_25]
R109  0  [RC0402_25]
R110  0  [RC0402_25]
R111  0  [RC0402_25]
R112  0  [RC0402_25]
R113  0  [RC0402_25]
R115  10.0K  [RC0402_25]
R121  10.0K  [RC0402_25]
R132  10.0K  [RC0402_25]
R133  10.0K  [RC0402_25]
R135  100K  [RC0402_25]
R137  0  [RC0402_25]
R140  10.0K  [RC0402_25]
R258  510  [RC0402_25]
R259  1.00k  [RC0402_25]
R264  1.00k  [RC0402_25]
R265  510  [RC0402_25]
R266  47K  [RC0402_25]
R269  47K  [RC0402_25]
R291  10.0K  [RC0402_25]
R292  0  [RC0402_25]
R293  0  [RC0402_25]
R294  0  [RC0402_25]
R298  100K  [RC0402_25]
R300  0  [RC0402_25]
R301  100K  [RC0402_25]
R302  10.0K  [RC0402_25]
R310  100K  [RC0402_25]
R311  10.0K  [RC0402_25]
R381  10.0K  [RC0402_25]
R382  10.0K  [RC0402_25]
R383  100  [RC1206_OV]
R384  100  [RC1206_OV]
R391  10.0K  [RC0402_25]
R392  10.0K  [RC0402_25]
R393  100  [RC1206_OV]
TP3  TPAD_050  [TPAD_050]
TP23  TPAD_050  [TPAD_050]
TP36  TPAD_050  [TPAD_050]
TP37  TPAD_050  [TPAD_050]
TP38  TPAD_050  [TPAD_050]
TP39  TPAD_050  [TPAD_050]
TP42  TPAD_050  [TPAD_050]
TP43  TPAD_050  [TPAD_050]
TP49  TPAD_050  [TPAD_050]
TP50  TPAD_050  [TPAD_050]
TP51  TPAD_050  [TPAD_050]
TP53  TPAD_050  [TPAD_050]
U23  MC33PF8100EQES  [qfn56_0p5_8p1x8p1_ep5p1]  (sections A,B,C)
sheet P20_USB3.x_TYPE_C
U15  MIMX8QM6AVUFFAB  [imx8_bga_1313]  (sections A,B,C,D,E,F,G,H,I,J,K,L,M,N,O,P,Q,R,S,T,U)
sheet P29_MIPI_DSI_CONNECTORS
C241  10uF  [CC0603_OV]
C247  10uF  [CC0603_OV]
C248  10uF  [CC0603_OV]
C249  10uF  [CC0603_OV]
C257  10uF  [CC0603_OV]
C263  10uF  [CC0603_OV]
C264  10uF  [CC0603_OV]
C265  10uF  [CC0603_OV]
J4  75784-0136  [con_36_0p8_th]
J9  75784-0136  [con_36_0p8_th]
R200  4.7K  [RC0402_25]
R201  4.7K  [RC0402_25]
R215  4.7K  [RC0402_25]
R216  4.7K  [RC0402_25]
sheet P30_B2B_CONNETOR
C11  10uF  [0603_CC]
C12  10uF  [0603_CC]
C13  10uF  [0603_CC]
C14  10uF  [0603_CC]
C17  10uF  [0603_CC]
C18  10uF  [0603_CC]
C19  10uF  [0603_CC]
C34  0.22uF  [CC0402_25]
C67  10uF  [CC0603_OV]
C86  10uF  [CC0603_OV]
J20  SEAF-50-05.0-L-06-2-A-K-TR  [con300_1p27_sm_seaf]  (sections A,B,C,D,E,F)
R46  4.7K  [RC0402_25]
R78  1.5K  [RC0402_25]
R154  4.7K  [RC0402_25]
R377  10.0K  [RC0402_25]
R378  10.0K  [RC0402_25]
TP5  TPAD_050  [TPAD_050]
TP9  TPAD_050  [TPAD_050]
TP12  TPAD_050  [TPAD_050]
TP13  TPAD_050  [TPAD_050]
TP14  TPAD_050  [TPAD_050]
TP29  TPAD_050  [TPAD_050]
TP30  TPAD_050  [TPAD_050]
TP31  TPAD_050  [TPAD_050]
TP32  TPAD_050  [TPAD_050]
TP34  TPAD_050  [TPAD_050]
TP35  TPAD_050  [TPAD_050]
TP40  TPAD_050  [TPAD_050]
TP41  TPAD_050  [TPAD_050]
TP44  TPAD_050  [TPAD_050]
TP45  TPAD_050  [TPAD_050]
TP54  TPAD_050  [TPAD_050]
TP55  TPAD_050  [TPAD_050]
TP57  TPAD_050  [TPAD_050]
TP58  TPAD_050  [TPAD_050]
TP59  TPAD_050  [TPAD_050]
TP60  TPAD_050  [TPAD_050]
TP65  TPAD_050  [TPAD_050]
TP67  TPAD_050  [TPAD_050]
TP68  TPAD_050  [TPAD_050]
TP84  TPAD_050  [TPAD_050]

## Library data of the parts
C70 C73 C74 C82 = CAP_NP: CAP CER 4.7uF 10V 10% X5R 0402; AGILE_PN: 150-79778; CAD_APPROVED: Yes; EN: 102-1-02063; FPLIST: CC0402_25,CC0402_HD,0402_CC; HEIGHT: 0.65MM; MFG_NAME01: TDK; MFG_PN01: C1005X5R1A475K050BC; ROHS: Yes; TOL: 10%; Tolerance: 10%; VOLTAGE: 10V
C71 C72 C75 C91 C94 C458 = CAP_NP: CAP CER 1uF 16V 10% X5R 0402; AGILE_PN: 150-79794; CAD_APPROVED: Yes; EN: 102-1-01641; FPLIST: CC0402_25,CC0402_HD,0402_CC; HEIGHT: 0.55MM; MFG_NAME01: NIC COMPONENTS CORP; MFG_PN01: NMC0402X5R105K16TRPF; ROHS: Yes; TOL: +/-10%; Tolerance: +/-10%; VOLTAGE: 16V
C83 C90 C95 C116 = CAP_NP: CAP CER 100UF 10V 10% X7R 1210; AGILE_PN: 150-75975; CAD_APPROVED: Yes; EN: 102-1-02315; FPLIST: CC1210,1210_CC; HEIGHT: 2.413MM; MFG_NAME01: CAPAX TECHNOLOGIES INC.; MFG_PN01: 1210X107K100SNT; ROHS: Yes; TOL: 10%; Tolerance: 10%; VOLTAGE: 10V
C96 C97 = CAP_NP: CAP CER 22uF 10V 20% X5R 0603; AGILE_PN: 150-79530; CAD_APPROVED: Yes; EN: 102-1-01791; FPLIST: CC0603_OV,CC0603,0603_CC; HEIGHT: 1MM; MFG_NAME01: TDK; MFG_PN01: C1608X5R1A226M080AC; ROHS: Yes; TOL: 20%; Tolerance: 20%; VOLTAGE: 10V
C98 C101 = CAP_NP: CAP CER 0.22uF 10V 10% X7R AEC-Q200 0402; AGILE_PN: 150-79031; CAD_APPROVED: Yes; EN: 102-1-01816; FPLIST: CC0402_25,CC0402_HD,0402_CC; HEIGHT: 0.55MM; MFG_NAME01: TDK; MFG_PN01: CGA2B1X7R1A224K050BC; ROHS: Yes; TOL: 10%; Tolerance: 10%; VOLTAGE: 10V
C99 = CAP_NP: CAP CER 2.2UF 6.3V 20% X5R 0402; AGILE_PN: 150-76792; CAD_APPROVED: Yes; EN: 102-1-01843; FPLIST: CC0402_25,CC0402_HD,0402_CC; HEIGHT: 0.55MM; MFG_NAME01: KEMET; MFG_PN01: C0402C225M9PACTU; ROHS: Yes; TOL: 20%; Tolerance: 20%; VOLTAGE: 6.3V
C439-C441 C454 C460-C462 = CAP_NP: CAP CER 4.7uF 16V 10% X5R 0603; AGILE_PN: 150-78976; CAD_APPROVED: Yes; EN: 102-1-00091; FPLIST: CC0603_OV,CC0603,0603_CC; HEIGHT: 0.9 MM; MFG_NAME01: TDK; MFG_PN01: C1608X5R1C475K080AC; ROHS: Yes; TOL: 10%; Tolerance: 10%; VOLTAGE: 16V
C445 C446 C449 C450 C453 C456 C457 = CAP_NP: CAP CER 0.1UF 16V 10% X7R 0402; AGILE_PN: 150-75182; CAD_APPROVED: Yes; EN: 102-1-01629; FPLIST: CC0402_25,CC0402_HD,0402_CC; HEIGHT: 0.635MM; MFG_NAME01: AVX; MFG_PN01: 0402YC104KAT2A; ROHS: Yes; TOL: 10%; Tolerance: 10%; VOLTAGE: 16V
L9-L15 = INDUCTOR: IND PWR 1.0uH@1MHZ 4.7A 20% AEC-Q200 SMD; AGILE_PN: 180-78525; CAD_APPROVED: Yes; EN: 103-1-00575; HEIGHT: 1.2MM; MFG_NAME01: TDK; MFG_PN01: TFM252012ALMA1R0MTAA; ROHS: Yes; TOL: 20%
Q5 Q7 Q11-Q14 = NMOS_NX3008NBK: TRAN NMOS PWR 30V 400mA AEC-Q101 SOT23; AGILE_PN: 480-79305; CAD_APPROVED: Yes; EN: 107-2-00226; FPLIST: SOT23_A,TO-236; HEIGHT: 1.1MM; MFG_NAME01: NEXPERIA; MFG_PN01: NX3008NBK,215; ROHS: Yes
Q6 Q8 = FDMS6681Z: TRAN PMOS PWR 49A 30V POWER56; AGILE_PN: 480-77938; CAD_APPROVED: Yes; EN: 107-2-00157; HEIGHT: 1.10MM; MFG_NAME01: FAIRCHILD; ROHS: Yes
R108-R112 R137 R292 R293 R300 = RES: RES MF ZERO OHM 1/16W -- AEC-Q200 0402; AGILE_PN: 470-80742; CAD_APPROVED: Yes; EN: 101-1-00001; FPLIST: RC0402_25,RC0402_HD,0402_CC; HEIGHT: 0.45 MM; MFG_NAME01: VISHAY INTERTECHNOLOGY; MFG_PN01: CRCW04020000Z0ED; ROHS: Yes
R113 R294 = RES: RES MF ZERO OHM 1/16W -- AEC-Q200 0402; AGILE_PN: 470-80742; ASSY_OPT: DNP; CAD_APPROVED: Yes; EN: 101-1-00001; FPLIST: RC0402_25,RC0402_HD,0402_CC; HEIGHT: 0.45 MM; MFG_NAME01: VISHAY INTERTECHNOLOGY; MFG_PN01: CRCW04020000Z0ED; ROHS: Yes
R115 R140 R291 R302 R311 R378 = RES: RES MF 10.0K 1/16W 1% 0402; AGILE_PN: 470-80574; ASSY_OPT: DNP; CAD_APPROVED: Yes; EN: 101-1-00389; FPLIST: RC0402_25,RC0402_HD,0402_CC; HEIGHT: 0.4MM; MFG_NAME01: WALSIN TECHNOLOGY CORP.; MFG_PN01: WR04X1002FTL; ROHS: Yes; TOL: 1%; Tolerance: 1%
R121 R132 R133 R377 R381 R382 R391 R392 = RES: RES MF 10.0K 1/16W 1% 0402; AGILE_PN: 470-80574; CAD_APPROVED: Yes; EN: 101-1-00389; FPLIST: RC0402_25,RC0402_HD,0402_CC; HEIGHT: 0.4MM; MFG_NAME01: WALSIN TECHNOLOGY CORP.; MFG_PN01: WR04X1002FTL; ROHS: Yes; TOL: 1%; Tolerance: 1%
R135 R298 R301 R310 = RES: RES MF 100K 1/16W 5% 0402; AGILE_PN: 470-75597; CAD_APPROVED: Yes; EN: 101-1-02817; FPLIST: RC0402_25,RC0402_HD,0402_CC; HEIGHT: 0.40 MM; MFG_NAME01: VENKEL COMPANY; MFG_PN01: CR0402-16W-104JT; ROHS: Yes; TOL: 5%; Tolerance: 5%
R258 R265 = RES: RES MF 510 OHM 1/16W 5% AEC-Q200 0402; AGILE_PN: 470-80690; CAD_APPROVED: Yes; EN: 101-1-02762; FPLIST: RC0402_25,RC0402_HD,0402_CC; HEIGHT: 0.4MM; MFG_NAME01: VISHAY INTERTECHNOLOGY; MFG_PN01: CRCW0402510RJNED; ROHS: Yes; TOL: 1%; Tolerance: 1%
R259 R264 = RES: RES MF 1.00k Ohm 1/16W 1% AEC-Q200 0402; AGILE_PN: 470-80511; CAD_APPROVED: Yes; EN: 101-1-00293; FPLIST: RC0402_25,RC0402_HD,0402_CC; HEIGHT: 0.4 MM; MFG_NAME01: KOA SPEER; MFG_PN01: RK73H1ETTP1001F; ROHS: Yes; TOL: 1%; Tolerance: 1%
R266 R269 = RES: RES MF 47K 1/10W 1% AEC-Q200 0402; AGILE_PN: 470-81731; CAD_APPROVED: Yes; EN: 101-1-03402; FPLIST: RC0402_25,RC0402_HD,0402_CC; HEIGHT: 0.40 MM; MFG_NAME01: KOA SPEER; MFG_PN01: RK73H1ETTP4702F; ROHS: Yes; TOL: 1%; Temp_Range: -55C to +155C; Tolerance: 1%
R383 R384 R393 = RES: RES MF 100 OHM 1/2W 1% 1206; AGILE_PN: 470-81826; CAD_APPROVED: Yes; EN: 101-1-03252; FPLIST: RC1206_OV,RC1206,1206_CC; HEIGHT: 0.65MM; MFG_NAME01: WALSIN TECHNOLOGY CORP.; MFG_PN01: WF12P1000FTL; ROHS: Yes; TOL: 1%; Temp_Range: -55C to +155C; Tolerance: 1%
TP3 TP5 TP9 TP12-TP14 TP23 TP29-TP32 TP34-TP45 TP49-TP51 TP53-TP55 TP57-TP60 TP65 TP67 TP68 TP84 = TESTLOOP: TEST POINT PAD 50MIL DIA SMT, NO PART TO ORDER; AGILE_PN: 211-76644; CAD_APPROVED: Yes; HEIGHT: 0.1MM; MFG_NAME01: NOTACOMPONENT; MFG_PN01: NOTACOMPONENT; ROHS: Yes
U23 = PC33PF8100A0ES_QFN56: IC POWER MANAGEMENT 2.5-5.5V AEC-Q100 QFN56; AGILE_PN: 315-82481; CAD_APPROVED: Yes; HEIGHT: 1 MM; MFG_NAME01: NXP SEMICONDUCTORS; Package Size: 8 mm x 8 mm x 0.85 mm; ROHS: Yes
U15 = PIMX8QM6AVUFFAB_BGA1313: IC CPU QUADMAX 2xA72 1.6GHz 4xA53 1.2GHZ M4 264MHZ FCPBGA1313; AGILE_PN: 330-77094; CAD_APPROVED: Yes; HEIGHT: 2.52MM; MFG_NAME01: NXP SEMICONDUCTORS; ROHS: Yes; Temp Range: -40°C to 125°C
C86 C241 C257 = CAP_NP: CAP CER 10uF 25V 20% X5R 0603; AGILE_PN: 150-79272; CAD_APPROVED: Yes; EN: 102-1-01982; FPLIST: CC0603_OV,CC0603,0603_CC; HEIGHT: 1MM; MFG_NAME01: Murata; MFG_PN01: GRM188R61E106MA73D; ROHS: Yes; TOL: 20%; Tolerance: 20%; VOLTAGE: 25V
C247-C249 C263-C265 = CAP_NP: CAP CER 10UF 10V 20% X5R 0603; AGILE_PN: 150-78609; CAD_APPROVED: Yes; EN: 102-1-01640; FPLIST: CC0603_OV,CC0603,0603_CC; HEIGHT: 1.016MM; MFG_NAME01: TAIYO YUDEN; MFG_PN01: LMK107BJ106MALTD; ROHS: Yes; VOLTAGE: 10V
J4 J9 = CONN_36_SH8_A: CON 36 MINISAS SHLD 0.8MM SP 800H AU 77L; AGILE_PN: 211-80162; CAD_APPROVED: Yes; EN: 201-1-00825; HEIGHT: 20.31MM; MFG_NAME01: MOLEX; ROHS: Yes
R46 R154 R200 R201 R215 R216 = RES: RES MF 4.7K 1/16W 5% 0402; AGILE_PN: 470-75626; CAD_APPROVED: Yes; EN: 101-1-02785; FPLIST: RC0402_25,RC0402_HD,0402_CC,RC0402_X2; HEIGHT: 0.41mm; MFG_NAME01: NIC COMPONENTS CORP; MFG_PN01: NRCL04J472TRF; ROHS: Yes; TOL: 5%; Tolerance: 5%
C11 C12 C17-C19 = CAP_NP: CAP CER 10UF 10V 20% X5R 0603; AGILE_PN: 150-78609; ASSY_OPT: DNP; CAD_APPROVED: Yes; EN: 102-1-01640; FPLIST: CC0603_OV,CC0603,0603_CC; HEIGHT: 1.016MM; MFG_NAME01: TAIYO YUDEN; MFG_PN01: LMK107BJ106MALTD; ROHS: Yes; VOLTAGE: 10V
C13 C14 C67 = CAP_NP: CAP CER 10uF 25V 20% X5R 0603; AGILE_PN: 150-79272; ASSY_OPT: DNP; CAD_APPROVED: Yes; EN: 102-1-01982; FPLIST: CC0603_OV,CC0603,0603_CC; HEIGHT: 1MM; MFG_NAME01: Murata; MFG_PN01: GRM188R61E106MA73D; ROHS: Yes; TOL: 20%; Tolerance: 20%; VOLTAGE: 25V
C34 = CAP_NP: CAP CER 0.22uF 10V 10% X7R AEC-Q200 0402; AGILE_PN: 150-79031; ASSY_OPT: DNP; CAD_APPROVED: Yes; EN: 102-1-01816; FPLIST: CC0402_25,CC0402_HD,0402_CC; HEIGHT: 0.55MM; MFG_NAME01: TDK; MFG_PN01: CGA2B1X7R1A224K050BC; ROHS: Yes; TOL: 10%; Tolerance: 10%; VOLTAGE: 10V
J20 = CONN_6X50_SEAF: CON 6X50 SHRD SKT SMT 1.27MM 209H AU; AGILE_PN: 211-80154; CAD_APPROVED: Yes; EN: 201-1-01068; HEIGHT: 5.3MM; MFG_NAME01: SAMTEC; MFG_PN01: SEAF-50-05.0-L-06-2-A-K; ROHS: Yes; Temp_Range: -55DegC to +125DegC
R78 = RES: RES MF 1.5K 1/16W 1% 0402; AGILE_PN: 470-80487; CAD_APPROVED: Yes; EN: 101-1-00310; FPLIST: RC0402_25,RC0402_HD,0402_CC; HEIGHT: 0.4MM; MFG_NAME01: BOURNS; MFG_PN01: CR0402-FX-1501GLF; ROHS: Yes; TOL: 1%; Tolerance: 1%

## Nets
GND: C11.2 C12.2 C13.2 C14.2 C17.2 C18.2 C19.2 C34.1 C67.2 C70.2 C71.2 C72.2 C73.2 C74.2 C75.2 C82.2 C83.2 C86.2 C90.2 C91.2 C94.2 C95.2 C96.2 C97.2 C98.2 C99.2 C101.2 C116.2 C241.1 C247.1 C248.1 C249.1 C257.1 C263.1 C264.1 C265.1 C439.1 C440.1 C441.1 C445.2 C446.2 C449.2 C450.2 C453.2 C454.1 C456.2 C457.2 C458.2 C460.1 C461.1 C462.1 J4.A1 J4.A4 J4.A7 J4.A12 J4.A15 J4.A18 J4.B1 J4.B4 J4.B7 J4.B12 J4.B15 J4.B18 J4.T1(SH1) J4.T2(SH2) J4.T3(SH3) J4.T4(SH4) J4.T5(SH5) J4.T6(SH6) J4.T7(SH7) J4.T8(SH8) J9.A1 J9.A4 J9.A7 J9.A12 J9.A15 J9.A18 J9.B1 J9.B4 J9.B7 J9.B12 J9.B15 J9.B18 J9.T1(SH1) J9.T2(SH2) J9.T3(SH3) J9.T4(SH4) J9.T5(SH5) J9.T6(SH6) J9.T7(SH7) J9.T8(SH8) J20.A3 J20.A4 J20.A7 J20.A8 J20.A12 J20.A15 J20.A18 J20.A21 J20.A24 J20.A27 J20.A30 J20.A33 J20.A36 J20.A39 J20.A40 J20.A43 J20.A44 J20.A47 J20.A48 J20.B3 J20.B4 J20.B7 J20.B8 J20.B10 J20.B13 J20.B16 J20.B19 J20.B22 J20.B25 J20.B28 J20.B31 J20.B34 J20.B37 J20.B38 J20.B41 J20.B42 J20.B45 J20.B46 J20.B49 J20.B50 J20.C3 J20.C4 J20.C7 J20.C8 J20.C12 J20.C15 J20.C18 J20.C21 J20.C24 J20.C27 J20.C30 J20.C33 J20.C36 J20.C39 J20.C42 J20.C45 J20.C48 J20.D3 J20.D4 J20.D7 J20.D8 J20.D10 J20.D13 J20.D16 J20.D19 J20.D22 J20.D25 J20.D28 J20.D31 J20.D34 J20.D37 J20.D40 J20.D43 J20.D46 J20.D49 J20.E3 J20.E4 J20.E7 J20.E8 J20.E12 J20.E15 J20.E18 J20.E21 J20.E24 J20.E27 J20.E30 J20.E33 J20.E36 J20.E39 J20.E42 J20.E45 J20.E48 J20.F3 J20.F4 J20.F7 J20.F8 J20.F10 J20.F13 J20.F16 J20.F19 J20.F22 J20.F25 J20.F28 J20.F31 J20.F34 J20.F37 J20.F40 J20.F43 J20.F46 J20.F49 Q5.2(SOURCE) Q7.2(SOURCE) Q11.2(SOURCE) Q12.2(SOURCE) Q13.2(SOURCE) Q14.2(SOURCE) R115.1 R121.1 R132.1 R135.2 R258.2 R265.2 R311.1 R378.1 U23.45(DGND) U23.51(AGND) U23.57(EP_GND) ; also on sheet 10 11 12 13 14 16 17 18 19 20 21 22 23 24 25 26 27 28 29 30 31 32
VCC_1V8: R46.2 R154.2 R391.2 ; also on sheet 10 11 12 15 16 17 18 19 21 24 27 28 31
VCC_3V3: C96.1 C97.1 L13.1 R259.2 R264.2 TP3.1(Pin1) U23.38(SW7FB) ; also on sheet 10 12 18 20 22 23 24 25 27 28 31
VCC_12V0: C13.1 C14.1 C241.2 C257.2 J4.A8 J4.A9 J9.A8 J9.A9 J20.A1 J20.A2 J20.B1 J20.B2 J20.C1 J20.C2 ; also on sheet 10 22 29 30
VCC_BB_ENT1IO: C86.1 J20.C37 J20.C38 ; also on sheet 12 31
VCC_DDRIO0: C90.1 L12.1 TP23.1(Pin1) U23.30(SW6FB) ; also on sheet 12 16
VCC_EXT_1V8: C17.1 C34.2 C247.2 C263.2 J4.A5 J4.A6 J9.A5 J9.A6 J20.D5 J20.D6 J20.E5 J20.E6 J20.F5 J20.F6 R200.2 R201.2 R215.2 R216.2 R393.1 ; also on sheet 10 14 29 30
VCC_EXT_3V3: Q6.1(S1) Q6.2(S2) Q6.3(S3) R269.2 R292.2 R392.2 ; also on sheet 10 11 18
VCC_EXT_5V0: C439.2 C440.2 C441.2 C445.1 C446.1 C449.1 C450.1 C453.1 C454.2 C456.1 C457.1 C458.1 C460.2 C461.2 C462.2 Q8.1(S1) Q8.2(S2) Q8.3(S3) R266.2 R294.2 U23.4(SW1IN) U23.7(SW2IN) U23.8(SW3IN) U23.11(SW4IN) U23.32(SW5IN) U23.35(SW6IN) U23.37(SW7IN) U23.50(VIN) ; also on sheet 10 11
VCC_GPU0: C116.1 L14.1 L15.1 TP53.1(Pin1) U23.2(SW2FB) U23.3(SW1FB) ; also on sheet 12
VCC_GPU1: C95.1 L9.1 L11.1 TP42.1(Pin1) U23.12(SW4FB) U23.13(SW3FB) ; also on sheet 12
VCC_LDO_SD2: R293.1 TP43.1(Pin1) ; also on sheet 12
VCC_LDO_SIM: J20.E9 R300.1 R377.2 TP37.1(Pin1) ; also on sheet 12
VCC_MEMC: C83.1 L10.1 TP36.1(Pin1) U23.31(SW5FB) ; also on sheet 12
VCC_PER_3V3: C18.1 C19.1 C248.2 C264.2 J4.A13 J4.A14 J9.A13 J9.A14 J20.A5 J20.A6 J20.B5 J20.B6 J20.C5 J20.C6 J20.E10 Q6.5(D) R78.2 R383.1 ; also on sheet 26 29 30 31
VCC_PER_5V0: C11.1 C12.1 C249.2 C265.2 J4.A16 J4.A17 J9.A16 J9.A17 J20.D1 J20.D2 J20.E1 J20.E2 J20.F1 J20.F2 Q8.5(D) R384.1 ; also on sheet 22 25 27 29 30
VCC_SCU_1V8: R133.1 R137.1 R291.1 R298.2 R301.2 R310.2 ; also on sheet 11 12 14 19 20 21
VCCA_PMIC2_1V5: C94.1 U23.41(V1P5A)
VCCD_PMIC2_1V5: C91.1 R140.1 R302.1 U23.40(V1P5D)
VDDOTP_PMIC2: R132.2 R140.2 U23.53(VDDOTP)
AMUX_PMIC2: TP51.1(Pin1) U23.52(AMUX)
B2B_TP1: J20.A9 TP14.1(Pin1)
B2B_TP2: J20.B9 TP12.1(Pin1)
B2B_TP3: J20.C9 TP9.1(Pin1)
B2B_TP4: J20.D9 TP5.1(Pin1)
B2B_TP6: J20.F9 TP13.1(Pin1)
BB_ARD_MIK_RST_B: J20.D41 ; also on sheet 24
BB_ARD_MIK_UART3_RX: J20.A34 ; also on sheet 15
BB_ARD_MIK_UART3_TX: J20.A35 ; also on sheet 15
BB_AUD_PWR_PWM(GPT1_COMPARE): J20.E31 ; also on sheet 15
BB_AUDIN_RST_B(QSPI1A_DATA1): J20.C32 ; also on sheet 19
BB_CAN0_RX: J20.C25 ; also on sheet 15
BB_CAN0_TX: J20.C26 ; also on sheet 15
BB_CAN1_RX: J20.C11 ; also on sheet 15
BB_CAN1_TX: J20.C10 ; also on sheet 15
BB_CAN2_RX: J20.C14 ; also on sheet 15
BB_CAN2_TX: J20.C13 ; also on sheet 15
BB_ENET1_MDC: J20.D47 ; also on sheet 24
BB_ENET1_MDIO: J20.D48 ; also on sheet 24
BB_ENET1_RGMII_RX_CTL: J20.F33 ; also on sheet 24
BB_ENET1_RGMII_RXC: J20.F38 ; also on sheet 24
BB_ENET1_RGMII_RXD0: J20.F30 ; also on sheet 24
BB_ENET1_RGMII_RXD1: J20.F35 ; also on sheet 24
BB_ENET1_RGMII_RXD2: J20.F32 ; also on sheet 24
BB_ENET1_RGMII_RXD3: J20.F29 ; also on sheet 24
BB_ENET1_RGMII_TX_CTL: J20.F42 ; also on sheet 31
BB_ENET1_RGMII_TXC: J20.F44 ; also on sheet 31
BB_ENET1_RGMII_TXD0: J20.F41 ; also on sheet 31
BB_ENET1_RGMII_TXD1: J20.F39 ; also on sheet 31
BB_ENET1_RGMII_TXD2: J20.F27 ; also on sheet 31
BB_ENET1_RGMII_TXD3: J20.F36 ; also on sheet 31
BB_ENET_DETECT_B: J20.E20 R78.1 ; also on sheet 12
BB_ESAI0_FSR: J20.D24 ; also on sheet 14
BB_ESAI0_FST: J20.D20 ; also on sheet 14
BB_ESAI0_MCLK: J20.A17 ; also on sheet 31
BB_ESAI0_SCKR: J20.D18 ; also on sheet 14
BB_ESAI0_SCKT: J20.D17 ; also on sheet 14
BB_ESAI0_TX0: J20.D21 ; also on sheet 14
BB_ESAI0_TX1: J20.D15 ; also on sheet 14
BB_ESAI0_TX2_RX3: J20.D26 ; also on sheet 14
BB_ESAI0_TX3_RX2: J20.D14 ; also on sheet 14
BB_ESAI0_TX4_RX1: J20.D23 ; also on sheet 14
BB_ESAI0_TX5_RX0: J20.D12 ; also on sheet 14
BB_ESAI1_FSR: J20.F14 ; also on sheet 14
BB_ESAI1_FST: J20.F12 ; also on sheet 14
BB_ESAI1_RX0: J20.F26 ; also on sheet 14
BB_ESAI1_RX1: J20.F18 ; also on sheet 14
BB_ESAI1_SCKR: J20.F15 ; also on sheet 14
BB_ESAI1_SCKT: J20.F20 ; also on sheet 14
BB_ESAI1_TX0: J20.F11 ; also on sheet 14
BB_ESAI1_TX1: J20.F17 ; also on sheet 14
BB_ESAI1_TX2: J20.F24 ; also on sheet 14
BB_ESAI1_TX3: J20.F23 ; also on sheet 14
BB_EXP_INT_1V8(SCU_GPIO0_06): J20.C28 ; also on sheet 14
BB_GPIO1(SPDIF0_EXT_CLK): J20.D44 ; also on sheet 14
BB_GPIO_1V8(ADC_IN0): J20.A31 ; also on sheet 15
BB_GPIO_1V8(EMMC0_RESET_B): J20.D11 ; also on sheet 18
BB_GPIO_1V8(LVDS1_I2C0_SCL): J20.D30 ; also on sheet 29
BB_GPIO_1V8(USDHC1_DATA4): J20.B12 ; also on sheet 18
BB_GPIO_1V8(USDHC1_DATA5): J20.C23 ; also on sheet 18
BB_GPIO_3V3(QSPI1A_DATA2): J20.C43 ; also on sheet 19
BB_GPIO_3V3(QSPI1A_DATA3): J20.C44 ; also on sheet 19
BB_GPIO_3V3(QSPI1A_SS1_B): J20.D29 ; also on sheet 19
BB_I2C0_3V3_SCL: J20.E34 ; also on sheet 31
BB_I2C0_3V3_SDA: J20.E35 ; also on sheet 31
BB_I2C4_3V3_SCL: J20.E22 ; also on sheet 31
BB_I2C4_3V3_SDA: J20.E23 ; also on sheet 31
BB_IOEXP_CAN_INT_B(GPT1_CLK): J20.B11 R46.1 ; also on sheet 15
BB_IOEXP_INT_B(GPT1_CAPTURE): J20.D50 R154.1 ; also on sheet 15
BB_M41_I2C0_1V8_SCL: J20.A22 ; also on sheet 15
BB_M41_I2C0_1V8_SDA: J20.A23 ; also on sheet 15
BB_MCLK_IN(MCLK_IN0): J20.A26 ; also on sheet 14
BB_MCLKIN1(SPDIF0_RX): J20.A19 ; also on sheet 14
BB_MCLKOUT1(SPDIF0_TX): J20.A20 ; also on sheet 14
BB_MKBUS_INT_1V8(SCU_GPIO0_04): J20.D27 ; also on sheet 14
BB_MLB_CLK: J20.F47 ; also on sheet 15
BB_MLB_CLK_N: J20.B43 ; also on sheet 15
BB_MLB_CLK_P: J20.B44 ; also on sheet 15
BB_MLB_DATA: J20.F45 ; also on sheet 15
BB_MLB_DATA_N: J20.B40 ; also on sheet 15
BB_MLB_DATA_P: J20.B39 ; also on sheet 15
BB_MLB_INT_B(USDHC1_STROBE): J20.B35 ; also on sheet 18
BB_MLB_SIG: J20.F50 ; also on sheet 15
BB_MLB_SIG_N: J20.B47 ; also on sheet 15
BB_MLB_SIG_P: J20.B48 ; also on sheet 15
BB_PCIE_CTRL1_CLKREQ_B: J20.B20 ; also on sheet 23
BB_PCIE_CTRL1_PERST_B: J20.B23 ; also on sheet 23
BB_PCIE_CTRL1_WAKE_B: J20.B21 ; also on sheet 23
BB_PCIE_RFCLK100M_PCIe_N: J20.A50 ; also on sheet 23
BB_PCIE_RFCLK100M_PCIe_P: J20.A49 ; also on sheet 23
BB_PCIE_RX0_N: J20.A45 ; also on sheet 23
BB_PCIE_RX0_P: J20.A46 ; also on sheet 23
BB_PCIE_TX0_N: J20.A41 ; also on sheet 23
BB_PCIE_TX0_P: J20.A42 ; also on sheet 23
BB_PER_RST_B: J20.D45 ; also on sheet 31
BB_SIM_CLK: J20.E11 ; also on sheet 15
BB_SIM_INT_B: J20.E19 ; also on sheet 15
BB_SIM_IO: J20.E14 ; also on sheet 15
BB_SIM_PD: J20.E17 R377.1 R378.2 ; also on sheet 15
BB_SIM_POWER_EN: J20.E16 ; also on sheet 15
BB_SIM_RST: J20.E13 ; also on sheet 15
BB_SPI0_CS0: J20.E29 ; also on sheet 14
BB_SPI0_MISO: J20.E28 ; also on sheet 14
BB_SPI0_MOSI: J20.E26 ; also on sheet 14
BB_SPI0_SCLK: J20.E25 ; also on sheet 14
BB_SPI1_CLK(ADC_IN3): J20.A11 ; also on sheet 15
BB_SPI1_CS0(ADC_IN6): J20.A16 ; also on sheet 15
BB_SPI1_CS1(ADC_IN7): J20.A10 ; also on sheet 15
BB_SPI1_INT_1V8(SCU_GPIO0_05): J20.C29 ; also on sheet 14
BB_SPI1_SDI(ADC_IN5): J20.A14 ; also on sheet 15
BB_SPI1_SDO(ADC_IN4): J20.A13 ; also on sheet 15
BB_SPI2_CS0: J20.B17 ; also on sheet 14
BB_SPI2_MISO: J20.B15 ; also on sheet 14
BB_SPI2_MOSI: J20.B14 ; also on sheet 14
BB_SPI2_SCLK: J20.B18 ; also on sheet 14
BB_SPI3_CS0: J20.C20 ; also on sheet 14
BB_SPI3_CS1: J20.C22 ; also on sheet 14
BB_SPI3_INT_1V8(ADC_IN1): J20.A25 ; also on sheet 15
BB_SPI3_MISO: J20.C19 ; also on sheet 14
BB_SPI3_MOSI: J20.C17 ; also on sheet 14
BB_SPI3_SCLK: J20.C16 ; also on sheet 14
BB_TAMPER_IN0: J20.E46 ; also on sheet 14
BB_TAMPER_IN1: J20.E47 ; also on sheet 14
BB_TAMPER_OUT0: J20.E40 ; also on sheet 14
BB_TAMPER_OUT1: J20.E41 ; also on sheet 14
BB_UART2_RX: J20.A28 ; also on sheet 15
BB_UART2_TX: J20.A29 ; also on sheet 15
BB_UART4_RX_AUDIN: J20.C34 ; also on sheet 15
BB_UART4_TX_AUDIN: J20.C35 ; also on sheet 15
BB_USB_OTG1_DN: J20.A37 ; also on sheet 22
BB_USB_OTG1_DP: J20.A38 ; also on sheet 22
BB_USB_OTG1_FLT_B: J20.B36 ; also on sheet 14
BB_USB_OTG1_ID: J20.C41 ; also on sheet 22
BB_USB_OTG1_PWR_ON: J20.A32 ; also on sheet 22
BB_USDHC2_CD_B: J20.D42 ; also on sheet 18
BB_USDHC2_CLK: J20.D39 ; also on sheet 18
BB_USDHC2_CMD: J20.D36 ; also on sheet 18
BB_USDHC2_DAT0: J20.D33 ; also on sheet 18
BB_USDHC2_DAT1: J20.D38 ; also on sheet 18
BB_USDHC2_DAT2: J20.D32 ; also on sheet 18
BB_USDHC2_DAT3: J20.D35 ; also on sheet 18
ENET1_REFCLK: J20.C40 ; also on sheet 24
LX1_GPU0: L14.2 U23.5(SW1LX)
LX1_GPU1: L11.2 U23.9(SW3LX)
LX2_GPU0: L15.2 U23.6(SW2LX)
LX2_GPU1: L9.2 U23.10(SW4LX)
LX_3V3: L13.2 U23.36(SW7LX)
LX_DDRIO0: L12.2 U23.34(SW6LX)
LX_MEMC: L10.2 U23.33(SW5LX)
MIPI_DSI0_1_EN: J4.A11 J9.A11 ; also on sheet 29
MIPI_DSI0_BL_PWM: J9.B8 U15.BD30(MIPI_DSI0_GPIO0_00)
MIPI_DSI0_CLK_N: J9.A2 U15.BN27(MIPI_DSI0_CLK_N)
MIPI_DSI0_CLK_P: J9.A3 U15.BL27(MIPI_DSI0_CLK_P)
MIPI_DSI0_DATA0_N: J9.B2 U15.BM28(MIPI_DSI0_DATA0_N)
MIPI_DSI0_DATA0_P: J9.B3 U15.BK28(MIPI_DSI0_DATA0_P)
MIPI_DSI0_DATA1_N: J9.B5 U15.BM26(MIPI_DSI0_DATA1_N)
MIPI_DSI0_DATA1_P: J9.B6 U15.BK26(MIPI_DSI0_DATA1_P)
MIPI_DSI0_DATA2_N: J9.B13 U15.BN29(MIPI_DSI0_DATA2_N)
MIPI_DSI0_DATA2_P: J9.B14 U15.BL29(MIPI_DSI0_DATA2_P)
MIPI_DSI0_DATA3_N: J9.B16 U15.BN25(MIPI_DSI0_DATA3_N)
MIPI_DSI0_DATA3_P: J9.B17 U15.BL25(MIPI_DSI0_DATA3_P)
MIPI_DSI0_TS_INT_B: J9.B9 U15.BD28(MIPI_DSI0_GPIO0_01)
MIPI_DSI0_TS_SCL: J9.B11 R216.1 U15.BE29(MIPI_DSI0_I2C0_SCL)
MIPI_DSI0_TS_SDA: J9.B10 R215.1 U15.BE31(MIPI_DSI0_I2C0_SDA)
MIPI_DSI1_BL_PWM: J4.B8 U15.BM24(MIPI_DSI1_GPIO0_00)
MIPI_DSI1_CLK_N: J4.A2 U15.BH30(MIPI_DSI1_CLK_N)
MIPI_DSI1_CLK_P: J4.A3 U15.BG31(MIPI_DSI1_CLK_P)
MIPI_DSI1_DATA0_N: J4.B2 U15.BH32(MIPI_DSI1_DATA0_N)
MIPI_DSI1_DATA0_P: J4.B3 U15.BG33(MIPI_DSI1_DATA0_P)
MIPI_DSI1_DATA1_N: J4.B5 U15.BH28(MIPI_DSI1_DATA1_N)
MIPI_DSI1_DATA1_P: J4.B6 U15.BG29(MIPI_DSI1_DATA1_P)
MIPI_DSI1_DATA2_N: J4.B13 U15.BH34(MIPI_DSI1_DATA2_N)
MIPI_DSI1_DATA2_P: J4.B14 U15.BG35(MIPI_DSI1_DATA2_P)
MIPI_DSI1_DATA3_N: J4.B16 U15.BH26(MIPI_DSI1_DATA3_N)
MIPI_DSI1_DATA3_P: J4.B17 U15.BG27(MIPI_DSI1_DATA3_P)
MIPI_DSI1_TS_INT_B: J4.B9 U15.BK24(MIPI_DSI1_GPIO0_01)
MIPI_DSI1_TS_SCL: J4.B11 R201.1 U15.BE27(MIPI_DSI1_I2C0_SCL)
MIPI_DSI1_TS_SDA: J4.B10 R200.1 U15.BG25(MIPI_DSI1_I2C0_SDA)
PMIC2_FSOB: R301.1 U23.29(FSOB)
PMIC2_INT_B: R108.2 R298.1 ; also on sheet 11
PMIC2_LDO3: C73.1 TP38.1(Pin1) U23.25(LDO3OUT)
PMIC2_LDO4: C70.1 TP39.1(Pin1) U23.28(LDO4OUT)
PMIC2_PGOOD: R310.1 TP50.1(Pin1) U23.42(PGOOD)
PMIC2_SYNCIN: R135.1 U23.48(SYNCIN)
PMIC2_XINTB: TP49.1(Pin1) U23.39(XINTB)
PMIC_EWARN: R112.2 ; also on sheet 11 14
PMIC_I2C_SCL: U23.55(SCL) ; also on sheet 11 14
PMIC_I2C_SDA: U23.56(SDA) ; also on sheet 11 14
PMIC_NC2: U23.44(XFAILB) ; also on sheet 11
PMIC_POR_B_1V8: R111.2 ; also on sheet 11 14 20
PMIC_WDOG_IN: R113.2 ; also on sheet 11 20
SCU_PMIC_ON_REQ: R110.2 ; also on sheet 11 14
SCU_PMIC_STANDBY: R109.2 ; also on sheet 11 14 20
TBBEN_PMIC2: R121.2 R302.2 U23.14(TBBEN)
USB_OTG1_VBUS: C67.1 J20.C31 ; also on sheet 22
USDHC2_ENABLE: R133.2 R311.2 U23.43(LDO2EN)
USDHC2_VSELECT: R115.2 R291.2 U23.16(VSELECT) ; also on sheet 18
N16607662: C98.1 U23.46(LICELL)
N16607710: R110.1 U23.22(PWRON)
N16607718: C101.1 R137.2 U23.54(VDDIO)
N16607756: R109.1 U23.23(STANDBY)
N16607796: R111.1 U23.21(~{RESET}_MCU)
N16607892: R113.1 U23.19(WDI)
N16609349: R112.1 U23.20(EWARN)
N16609453: R108.1 U23.24(~{INT})
N16613519: C82.1 R300.2 U23.15(LDO1OUT)
N16613591: C71.1 C72.1 C75.1 R292.1 R294.1 U23.17(LDO12IN) U23.26(LDO3IN) U23.27(LDO4IN)
N16613599: C74.1 R293.2 U23.18(LDO2OUT)
N16616222: C99.1 U23.47(VSNVS)
N16634030: Q8.4(G) R266.1 R382.1
N16634034: Q6.4(G) R269.1 R381.1
N16634162: Q5.1(GATE) R258.1 R259.1
N17843716: J20.B24 TP30.1(Pin1)
N17843737: J20.B26 TP31.1(Pin1)
N17843752: J20.B27 TP32.1(Pin1)
N17843767: J20.B29 TP34.1(Pin1)
N17843782: J20.B30 TP35.1(Pin1)
N17843797: J20.B32 TP40.1(Pin1)
N17843812: J20.B33 TP41.1(Pin1)
N17843827: J20.C46 TP55.1(Pin1)
N17843842: J20.C47 TP58.1(Pin1)
N17843857: J20.C49 TP59.1(Pin1)
N17843872: J20.C50 TP65.1(Pin1)
N17843899: J20.E50 TP68.1(Pin1)
N17843914: J20.E49 TP67.1(Pin1)
N17843952: J20.E43 TP54.1(Pin1)
N17843954: J20.E44 TP57.1(Pin1)
N17843982: J20.E37 TP45.1(Pin1)
N17843984: J20.E38 TP44.1(Pin1)
N17844001: J20.F48 TP60.1(Pin1)
N17844016: J20.F21 TP29.1(Pin1)
N18406461: Q7.3(DRAIN) Q11.1(GATE) R381.2
N18419627: Q11.3(DRAIN) R383.2
N18419800: Q12.3(DRAIN) R384.2
N18419813: Q5.3(DRAIN) Q12.1(GATE) R382.2
N19196098: Q7.1(GATE) R264.1 R265.1
N20035042: J20.E32 TP84.1(Pin1)
N21104823: Q13.3(DRAIN) Q14.1(GATE) R392.1
N21105083: Q13.1(GATE) R391.1
N21105247: Q14.3(DRAIN) R393.2

Not connected (* = marked no-connect by the designer): J4 A10*; J9 A10*; U23 1(NC1)* 49(SYNCOUT)*

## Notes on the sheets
sheet 1
- MCIMX8QM-CPU MEK Platform
- Information in this schematic is provided as a courtesy to customers and is provided on an "as is" basis.
  NXP's warranty on products sold will not be expanded, and no obligation or liability will arise, due to
  technical advice, data, or other information provided herein or that NXP may otherwise provide in
  connection with this schematic.
- Schematic capture done with Allegro Design Entry CIS 17.2. Schematic also available in 16.2.
sheet 2
- B2B CONNECTOR
- EACH CONNECTOR PIN
  CAPABLE OF 1.2 A
- See note
  in box below.
- See note
  in box below.
- 6-Wire Differential MLB not supported by the processor.
  Adopters must follow the Hardware Developer’s Guide
  Unused input/output terminations section.
- Users can install both ENET and
  AUD cards simultaneously in BB
- SOME PINS ARE RESERVED TO FACILITATE A COMMON BASE BOARD FOR QM AND QXP.
- NXP is aware that the UART net names circled are inaccurate. There is
  no plan to change the net names.
  Adopters please note:
  UART3 net name on pins A34 & A35 should be UART4.
  UART4 net name on pins C34 & C35 should be UART3.
  2-Wire AUDIN function not available on Base Board.
- 3-Wire Single-Ended MLB not supported by the processor.
  Other functions are supported as determined by IOMUX selection.
  If unused, adopters must follow the Hardware Developer's
  Guide Unused input/output terminations section.
sheet 3
- i.MX 8QM CPU CARD I2C TABLE
- 8-bit write
  addresses
- DEVICE
  ADDRESS
- DEVICE
- Location
- Speed(kbps)
- I2C
- IO LEVEL
- PMIC1
- CPU
- 0x08
- PMIC I2C
- 1.8V
- 3400
- PMIC2
- CPU
- 3400
- 0x09
- PMIC I2C
- 1.8V
- FXOS8700CQ
- CPU
- 400
- 0x1E
- 0x1E
- I2C0
- 3.3V
- MPL3115A2
- CPU
- 400
- 0xC0
- 0x60
- I2C0
- 3.3V
- FXAS21002CQR1
- CPU
- 400
- 0x40
- 0x20
- I2C0
- 3.3V
- PTN5110
- CPU
- 400
- 0xA2
- 0x51
- I2C0
- 3.3V
- ARDUINO/MIKROBUS
- BASE
- I2C0
- 3.3V
- ENET CONN
- BASE
- I2C0
- 3.3V
- MLB*
- BASE
- 0x40
- I2C0
- 3.3V
- AUDIO IN/OUT
- BASE
- 0x90
- M41.I2C
- 1.8V
- WM8960
- CPU
- 0x34
- I2C1
- 1.8V
- AUX I2C
- BASE
- 0x20
- I2C4
- 3.3V
- * MLB is not supported by the processor.
sheet 4
- BLOCK DIAGRAM - RESET
sheet 5
- MIPI DSI CONNECTORS
- 100-Ohm
  differential
  pairs
- 100-Ohm
  differential
  pairs
sheet 6
- POWER SUPPLY - PMIC 2
- LOAD SWITCH FOR 3V3 PERIPHERALS
- LOAD SWITCH FOR 5V0 PERIPHERALS
- DISCHARGE CIRCUIT FOR EXT_1V8
sheet 7
- Power Flow Diagram
- Display Port
  Connector
- 8x Mini SAS
  Connectors
- ARDUINO
  MICROBUS
  HEADER
- Smart Card
- PMIC_3.3V I/O
- Audio In
  Connector
- RS232
- M.2
  Connector
- Enable
- PMIC1
- 3x CAN
- AUX
  12C
- LOAD
  SWITCH
- 8x Mini SAS
  Connectors
- ETHERNET
  Connector
- SD Card
- M.2
  Connector
- VIN
- SNVS
- VDD_SNVS
- Audio In
  Connector
- Audio Out
  Connector
- VDDIO
- 3.3V I/O Peripherals
- 12V INPUT
- Buck Regulator
       1.8V
- CPU FAN
- Type C
  Connector
- PMIC_1.8V_IO
- Enable
- SW 1& 2
- VDD_MAIN
- IR3827M
- 8x Mini SAS
  Connectors
- Audio Out
  Connector
- USDHC1_
  RESET_B
- SW 3 & 4
- CPU1
- Audio In
  Connector
- 3x CAN
- LPDDR4
- SW  6
- VDD_DDRIO1
- MT53B768M32D4DT-062
- 12V Peripherals
- Enable
- SW  7
- 1.8V I/O
- iMX8 QM Processor
- SD Card
- LOAD
  SWITCH
- Octel SPI
  MT35XU512ABA1G12-0AA
- DIN CON
    12V
- SW 5
- CPU0
- eMMC
  MTFC32GAKAEEF
- Buck Regulator
       3.3V
- LDO 1
- VDD_SCU_1V8
- Audio Codec
  WM8960CGEFL
- LDO 2
- SD0
- Enable
- IR3895M
- 1.8V I/O Peripherals
- LDO 3
- NO MOUNT
- Buck Regulator
        5V
- VIN
- VDDIO
- LPDDR4
- Enable
- IR3895M
- SW 6
- VDD_DDRIO0
- MT53B768M32D4DT-062
- SW 1 & 2
- GPU0
- PMIC_3.3V I/O
- SW 3 & 4
- GPU1
- Enable
- LOAD
  SWITCH
- CC Logic
  PTN5110THQ
- Status LEDs
- SW 5
- VDD_MEMC
- 1Gbps Ethernet
       AR8031
- Sensors
- SW  7
- 3.3V I/O
- HDMI
  Connector
- PCIe OSC
  DSC557-04444K
- USB Demux
  CBTL04GP043
- Type C
  Connector
- ARDUINO
  MICROBUS
  HEADER
- LDO 1
- VDD_SIM
- Audio Codec
  WM8960CGEFL
- eMMC
  MTFC32GAKAEEF
- Micro USB
  OTG
  Connector
- LDO 2
- SD1
- 3x CAN
  TJA1043T
- ETHERNET
  Connector
- EXT_LDO_1V2
   AP7217D
- Audio Codec
  WM8960CGEFL
- USB_HSIC0_1P2
- 3.3V I/O Peripherals
- Smart Card
- 8x Mini SAS
  Connectors
- Audio In
  Connector
- PMIC2
- 5V  Peripherals
- Note: Doted line represents components in Base Boad.
sheet 8
- Content
- REV
- Revision Notes
- Date
- Page No
- Sheet Name
- C1
- 1. Sheet No. 8 : Pull-Up Resistors removed from PMIC pin 1.
      Pin 44 tied to Pin 41, to minimize quiscent current
- 08-08-2018
- 01
- FRONT PAGE
- 2. Sheet No. 17 : SATA Boot Option removed from the boot mode list
- 3. Sheet No. 22 :1uF Capacitor is added in series with HDMI_RX0_ARC_P
      (For fixing HDMI RX side issues)
- 02
- TITLE PAGE
- 4. Sheet Nos. 9 & 16: Changed R383 from 1K to 100E,
      SD Card Power Changed from VCC_PER_3V3 to VCC_EXT_3V3
      and Discharge Circuit for EXT_1V8
      Added ( For fixing power discharge issues while Processor reset)
- 03
- BLOCK DIAGRAM
- i.MX 8QM CPU Card
- 04
- BLOCK DIAGRAM-POWER
- 5. Sheet No. 24 : Changed Headphone Jack Pinout to AHJ (Pins 1 & 4 Swapped)
      and added AHJ Graphic (Headphone JacK reconfiguration )
- 05
- BLOCK DIAGRAM-RESET
- 6. Sheet No. 19  : FTDI Chip updated to FT4232H
- 06
- I2C TABLE
- Part Number: MCIMX8QM-CPU
- 7. Sheet No. 30 : Connector J20 symbol updated
- 07
- POWER SUPPLY
- 8. Sheet Nos.12 & 19 : Option provided for connecting SCU UART
      signals to FTDI Chip for debug
- 08
- PMIC 1
- 9. Sheet No . 21 : PCIe clock selection ( internal / external ) option provided
- 10. Sheet No 9 : PMIC2 WDI disconnected as per PMIC errata ER023
      (R113 Unmounted)
- 09
- PMIC 2
- 11. Sheet Nos 14 & 15 : DDR_CH0_RST_B & DDR_CH1_RST_B
      Pulldown to Ground with 10K (Added R1481 & R1482 )
- 10
- MX8QM POWER
- This board was designed for maximum flexibility in software
  development and demonstrates multiple functions possible with
  i.MX processors. Although best design practices have been
  applied, some areas may not be suitable for a mass production
  design. For an added resource, refer to Hardware Development
  Guide document.
- 11
- MX8QM GND
- 12. Sheet Nos 12: Added R1483 & R1484 for ANA_TEST_OUT 0 and 1
- C2
- 1. Processor part number updated to "PIMX8QM6AVUFFAB"
- 17-09-2018
- 12
- MX8QM SECTIONS_1
- 13
- MX8QM SECTIONS_2
- C3
- C3 is internal release, not used for layout update.
- 22-Nov-2019
- 1. PMIC_1 (U10) P/N updated to MC33PF8100EPES
- PMIC_2 (U23) P/N updated to MC33PF8100EQES
- 14
- LPDDR4_DRAM_1
- 2. Following obsolete P/N updated:
- DA1,DA2 - BAV99LT1G (ON SEMICONDUCTOR)
- 15
- LPDDR4_DRAM_2
- Consumer devices were utilized in this design when lead time
  for equivalent automotive-grade devices conflicted with
  production schedules. NXP suggests consulting component
  suppliers for equivalent automotive-grade device information.
- J1,J6 - 47659-1100 (MOLEX)
- U17,U18 - MT53E768M32D4DT-053 AIT:E (MICRON)
- 16
- eMMC & SD CARD
- C4
- No electrical changes.
- 24-Jan-2020
- 17
- BOOT CONFIGURATIONS & SPI FLASH
- 1. Classification changed to Public Information.
- 2. Note updates.
- 18
- RESET & LEDs & JTAG
- 3. U15 Processor and U10/U23 PMICs updated to production part numbers.
- 19
- DEBUG UART TO USB
- 4. Following P/N updated back to:
- DA1,DA2 - BAV99 (FAIRCHILD)
- J1,J6 - 47659-1000 (MOLEX)
- 20
- USB3.x TYPE C
- 21
- PCIe & SATA
- Following Parts Updated:-
- 22
- HDMI TX & RX
- DNP appearing near a component signifies "do not populate."
  These parts are not installed
- 1. HDMI Connector J1 and J6 updated to 476591100. Footprint number differs
     from layout rev C1, but is compatible per CM.
- 23
- ETHERNET PHY
- 2. U37 updated to PTN5110NTHQZ
- C5
- 09-Jun-2020
- 24
- AUDIO CODEC WM8960
- 3. DA1 and DA2 updated to BAV99LT1G. Footprint number differs from layout
     rev C1, but is compatible per CM.
- 4. C531 made as DNP
  5. R369 value changed to 23.2K for increasing Current limit of load switch to 3A
- 25
- WIFI & BLUETOOTH
- 26
- SENSORS
- 27
- LVDS CONNECTORS
- No electrical changes.
  1. Processor does not support MLB; removed MLB from diagrams on
      sheets 3 & 4. Added notations on sheets 6, 10, 13, 16, 30.
  2. Added USB VBUS disable pull-down note & VBUS circuit (as a note) to sheet 20.
  3. Added UART3 & UART4 net name error notes to sheets 13 & 30.
- 28
- MIPI  CSI CONNECTORS
- C6
- 13-Jan-2021
- 29
- MIPI  DSI CONNECTORS
- 30
- BOARD TO BOARD CONNECTORS
- No electrical changes.
  1. Fixed BOM notation error on C547. The assembly option was "NM" and now
      changed to a blank field. This capacitor has always been installed. See sheet 20.
- 31
- LEVEL TRANSLATORS & DRIVERS
- C7
- 18-Jan-2021
- 32
- MISCELLANEOUS
- i.MX 8QXP CPU Card
- LVDS TO HDMI Daughter Card
- Schematic SCH-29683
  Part No. MCIMX8QXP-CPU
- Schematic SCH-29680
  Part No. IMX-LVDS-HDMI
- ENET Daughter Cards
- Common Base Board
- Schematic SCH-29918
  Part No. MCIMX8-8X-BB
- MIPI TO HDMI Daughter Card
- Audio IO Card
- Schematic SCH-29678
  Part No. IMX-MIPI-HDMI
- Schematic SCH-29941
  Part No. IMX-AUD-IO
- i.MX 8QM CPU Card
- Schematic SCH-29420
  Part No. MCIMX8QM-CPU
- Additional information on compatible daughter cards, cameras, etc. is provided on the nxp.com website.
sheet 9
- i.MX 8QM CPU BOARD BLOCK_DIAGRAM
- POWER SUPPLY
- PMIC_I2C_SCL
- 12V@7A
- DC-DC
  CONVERTER
- PF8100 (2x)
- PMIC_I2C_SDA
- 3.3V
- 1.8V
- 1.8V
- 1.1V
- LPDDR-4
  3GB, x32
- UART
- LPDDR4
- UART 0
- M4O UART 0
- FT4232H
- 1.8V
- SCU UART 0
- OCTAL
  SPI FLASH
  64MB
- QSPI0B
- TEST
  POINTs
- QSPI
- QSPI0A
- 3.3V
- 12V
- 5V
- eMMC
  32GB
- SCL
- EMMC0
- SDA
- PTN5110
- NX20P5090
- NX5P3290
- 3.3V
- 4 bit
- SDXC
- USB SS 3.0
- USB
- SCL
- CBTL04GP043EXJ
- USB conn:
  TYPE C
- SDA
- 3.3V
- 1.5V
- 2.5V
- USB OTG 2
- 1000 BASE-T
- RGMII0
- 5V
- 3.3V
- 1.8V
- AR8031
- MDC0
- ETHERNET
- MDIO0
- SAI1
- WM8960
- TO BASE
  BOARD
- SCL
- I2C 0
- BUFFER
- AUDIO
- SDA
- TO BASE
  BOARD
- RGMII1
- ESAI0
- JTAG
- i.MX8QM
- HDMI
  RX0
- SATA0
- HDMI
  TX0
- LEDs
- GPIOs
- SCUBOOT
  MODE
- PUSH
  BUTTONs
- LVDS0
  CH0
- DSI 1
- LVDS0
  CH1
- mSAS
- LVDS
- DSI 0
- mSAS
- MIPI
- LVDS1
  CH0
- CSI 1
- LVDS1
  CH1
- CSI 0
- PCIE
- ON BOARD
  SENSORS
- I2C 2
- UART
- M.2
  CONNECTOR
- I2S
- SDXC
- ARDUINO/
  MICROBUS
- SPI2
  UART3
- 4 bit
- SD2
- PCIE0
- TAMPER
- CAN
- I2C
  MODULE
- USB 2.0
  OTG
- UART
- ESAI1
- CAN0
- CAN1
- CAN2
- BASE BOARD CONNECTOR
